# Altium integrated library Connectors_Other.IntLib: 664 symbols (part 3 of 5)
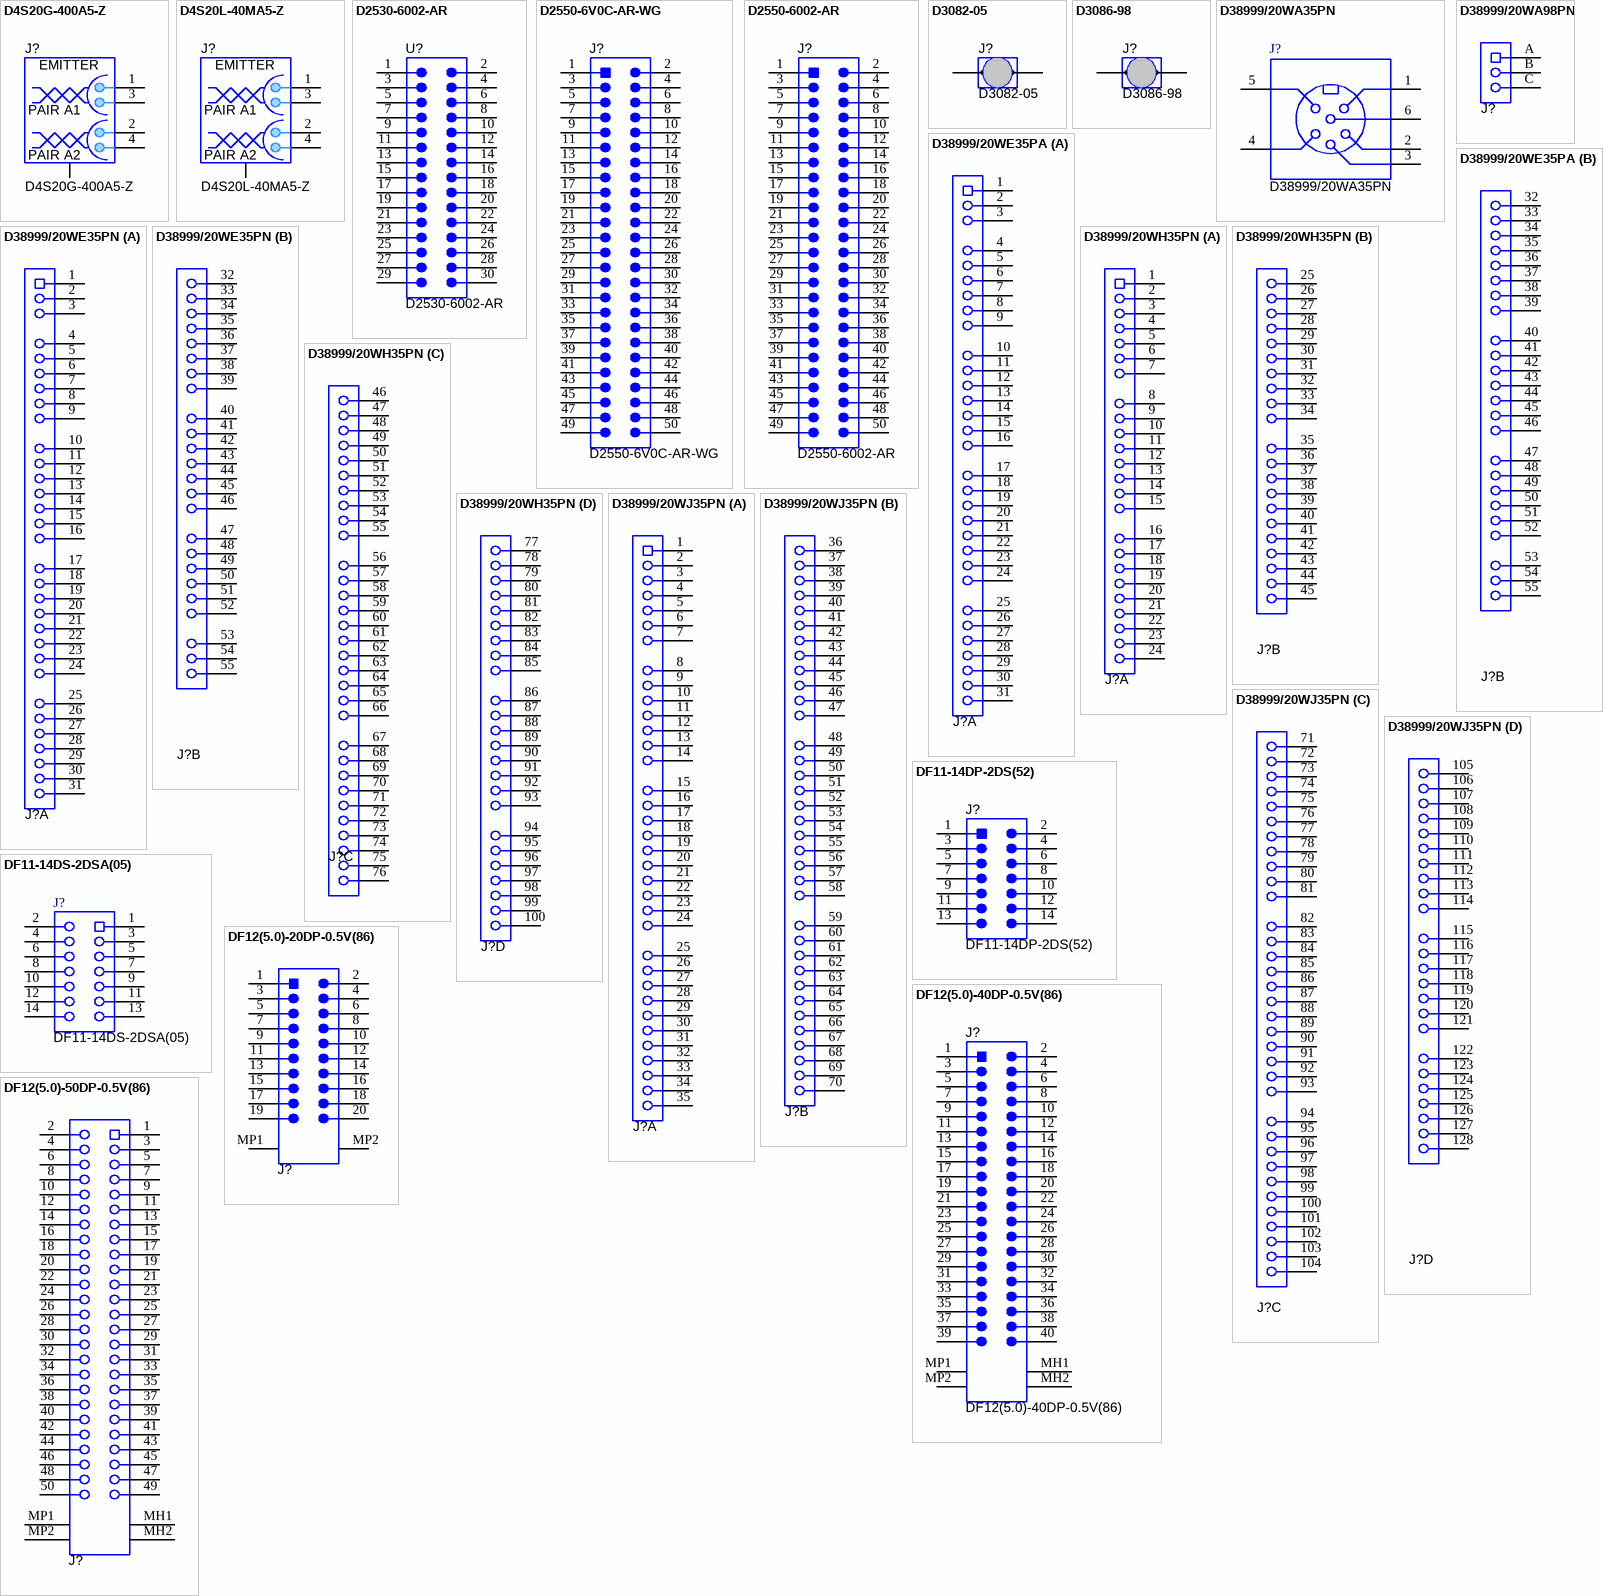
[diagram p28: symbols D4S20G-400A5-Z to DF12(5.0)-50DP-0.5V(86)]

## D3086-98
designator J?
1MM INSULATED SHORTING PLUG, TH; Manufacturer: Harwin; SymbolCreator: a0799628; CompType: Jumper Wire; Pitch_mm: 5.08; Row_Count: 1; ContactFinish: Gold; Green_Lifecycle: Active; Green_REACh: Passed
footprint Harwin_D3086-98
pins: 1, 2

## D38999/20WA35PN
designator J?
Receptacle, A35, 6 Pos, Gold, TH; Manufacturer: Amphenol Aerospace; SymbolCreator: x0208326; CompType: Connector; Gender: Female; Current_A: 5
footprint Amphenol_D38999_20WA35PN
pins: 1, 2, 3  , 4  , 5  , 6  

## D38999/20WA98PN
designator J?  (value not drawn)
Receptacle, A98, 3 Pos, Gold, TH; Manufacturer: Amphenol Aerospace; SymbolCreator: Altium; CompType: Connector; Gender: Female; Current_A: 7.5
footprint Amphenol_D38999_20WA98PN
pins: A, B, C

## D38999/20WE35PA
designator J?  (value not drawn)
Receptacle, E35, 55 Pos, Gold, TH; Manufacturer: Amphenol Aerospace; SymbolCreator: Altium; CompType: Connector; Gender: Female; Current_A: 5; Voltage_V: 550
footprint Amphenol_D38999_20WE35
part A pins: 1, 2, 3, 4, 5, 6, 7, 8, 9, 10, 11, 12, 13, 14, 15, 16, 17, 18, 19, 20, 21, 22, 23, 24, 25, 26, 27, 28, 29, 30, 31
part B pins: 32, 33, 34, 35, 36, 37, 38, 39, 40, 41, 42, 43, 44, 45, 46, 47, 48, 49, 50, 51, 52, 53, 54, 55

## D38999/20WE35PN
designator J?  (value not drawn)
Receptacle, E35, 55 Pos, Gold, TH; Manufacturer: Amphenol Aerospace; SymbolCreator: Altium; CompType: Connector; Gender: Female; Current_A: 5
footprint Amphenol_D38999_20WE35
part A pins: 1, 2, 3, 4, 5, 6, 7, 8, 9, 10, 11, 12, 13, 14, 15, 16, 17, 18, 19, 20, 21, 22, 23, 24, 25, 26, 27, 28, 29, 30, 31
part B pins: 32, 33, 34, 35, 36, 37, 38, 39, 40, 41, 42, 43, 44, 45, 46, 47, 48, 49, 50, 51, 52, 53, 54, 55

## D38999/20WH35PN
designator J?  (value not drawn)
Receptacle, H35, 100 Pos, Gold, TH; Manufacturer: Amphenol Aerospace; SymbolCreator: Altium; CompType: Connector; Gender: Female; Current_A: 5; Voltage_V: 550
footprint Amphenol_D38999_20WH35PN
part A pins: 1, 2, 3, 4, 5, 6, 7, 8, 9, 10, 11, 12, 13, 14, 15, 16, 17, 18, 19, 20, 21, 22, 23, 24
part B pins: 25, 26, 27, 28, 29, 30, 31, 32, 33, 34, 35, 36, 37, 38, 39, 40, 41, 42, 43, 44, 45
part C pins: 46, 47, 48, 49, 50, 51, 52, 53, 54, 55, 56, 57, 58, 59, 60, 61, 62, 63, 64, 65, 66, 67, 68, 69, 70, 71, 72, 73, 74, 75, 76
part D pins: 77, 78, 79, 80, 81, 82, 83, 84, 85, 86, 87, 88, 89, 90, 91, 92, 93, 94, 95, 96, 97, 98, 99, 100

## D38999/20WJ35PN
designator J?  (value not drawn)
Receptacle, J35, 128 Pos, Gold, TH; Manufacturer: Amphenol Aerospace; SymbolCreator: Altium; CompType: Connector; Gender: Female; Current_A: 5; Voltage_V: 550
footprint Amphenol_D38999_20WJ35PN
part A pins: 1, 2, 3, 4, 5, 6, 7, 8, 9, 10, 11, 12, 13, 14, 15, 16, 17, 18, 19, 20, 21, 22, 23, 24, 25, 26, 27, 28, 29, 30, 31, 32, 33, 34, 35
part B pins: 36, 37, 38, 39, 40, 41, 42, 43, 44, 45, 46, 47, 48, 49, 50, 51, 52, 53, 54, 55, 56, 57, 58, 59, 60, 61, 62, 63, 64, 65, 66, 67, 68, 69, 70
part C pins: 71, 72, 73, 74, 75, 76, 77, 78, 79, 80, 81, 82, 83, 84, 85, 86, 87, 88, 89, 90, 91, 92, 93, 94, 95, 96, 97, 98, 99, 100, 101, 102, 103, 104
part D pins: 105, 106, 107, 108, 109, 110, 111, 112, 113, 114, 115, 116, 117, 118, 119, 120, 121, 122, 123, 124, 125, 126, 127, 128

## DF11-14DP-2DS(52)
designator J?
Header (shrouded), 2 mm, 7x2, R/A, TH; Manufacturer: Hirose Electric Co. Ltd.; SymbolCreator: a0412235
footprint Hirose_DF11-14DP-2DS_52
pins: 1, 2, 3, 4, 5, 6, 7, 8, 9, 10, 11, 12, 13, 14

## DF11-14DS-2DSA(05)
designator J?
Receptacle, 2mm, 7x2, Gold, TH; Manufacturer: Hirose Electric Co. Ltd.; SymbolCreator: a0412235; Green_Lifecycle: Not Set; Green_REACh: Incomplete
footprint Hirose_DF11-14DS-2DSA[05]
pins: 1, 2, 3, 4, 5, 6, 7, 8, 9, 10, 11, 12, 13, 14

## DF12(5.0)-20DP-0.5V(86)
designator J?  (value not drawn)
Header(Shrouded), 0.5mm, 10x2, Gold, SMT; Manufacturer: Hirose Electric Co. Ltd.; SymbolCreator: Altium; Pitch_mm: 0.5; Gender: Male; Shrouded: Y; Row_Count: 2; Current_A: 0.3; Voltage_V: 50
footprint Hirose_DF12_5_0-20DP-0_5V
pins: 1, 2, 3, 4, 5, 6, 7, 8, 9, 10, 11, 12, 13, 14, 15, 16, 17, 18, 19, 20, MP1, MP2

## DF12(5.0)-40DP-0.5V(86)
designator J?
Header(shrouded), 0.5mm, 20x2, Gold, SMT; Manufacturer: Hirose Electric Co. Ltd.; SymbolCreator: Altium; Pitch_mm: 0.5; Gender: Male; Shrouded: Y; Row_Count: 2; Current_A: 0.3; Voltage_V: 50
footprint Hirose_DF12_5_0-40DP-0_5V
pins: 1, 2, 3, 4, 5, 6, 7, 8, 9, 10, 11, 12, 13, 14, 15, 16, 17, 18, 19, 20, 21, 22, 23, 24, 25, 26, 27, 28, 29, 30, 31, 32, 33, 34, 35, 36, 37, 38, 39, 40, MH1, MH2, MP1, MP2

## DF12(5.0)-50DP-0.5V(86)
designator J?  (value not drawn)
Receptacle, 0.5mm, 25x2, Gold, SMT; Manufacturer: Hirose Electric Co. Ltd.; SymbolCreator: Altium; Pitch_mm: 0.5; Gender: Female; Row_Count: 2; Current_A: 0.3; Voltage_V: 50; Cert_UL: Y
footprint Hirose_DF12_5_0-50DP-0_5V
footprint Hirose_DF12_5_0-50DP-0_5V_Reverse
pins: 1, 2, 3, 4, 5, 6, 7, 8, 9, 10, 11, 12, 13, 14, 15, 16, 17, 18, 19, 20, 21, 22, 23, 24, 25, 26, 27, 28, 29, 30, 31, 32, 33, 34, 35, 36, 37, 38, 39, 40, 41, 42, 43, 44, 45, 46, 47, 48, 49, 50, MH1, MH2, MP1, MP2

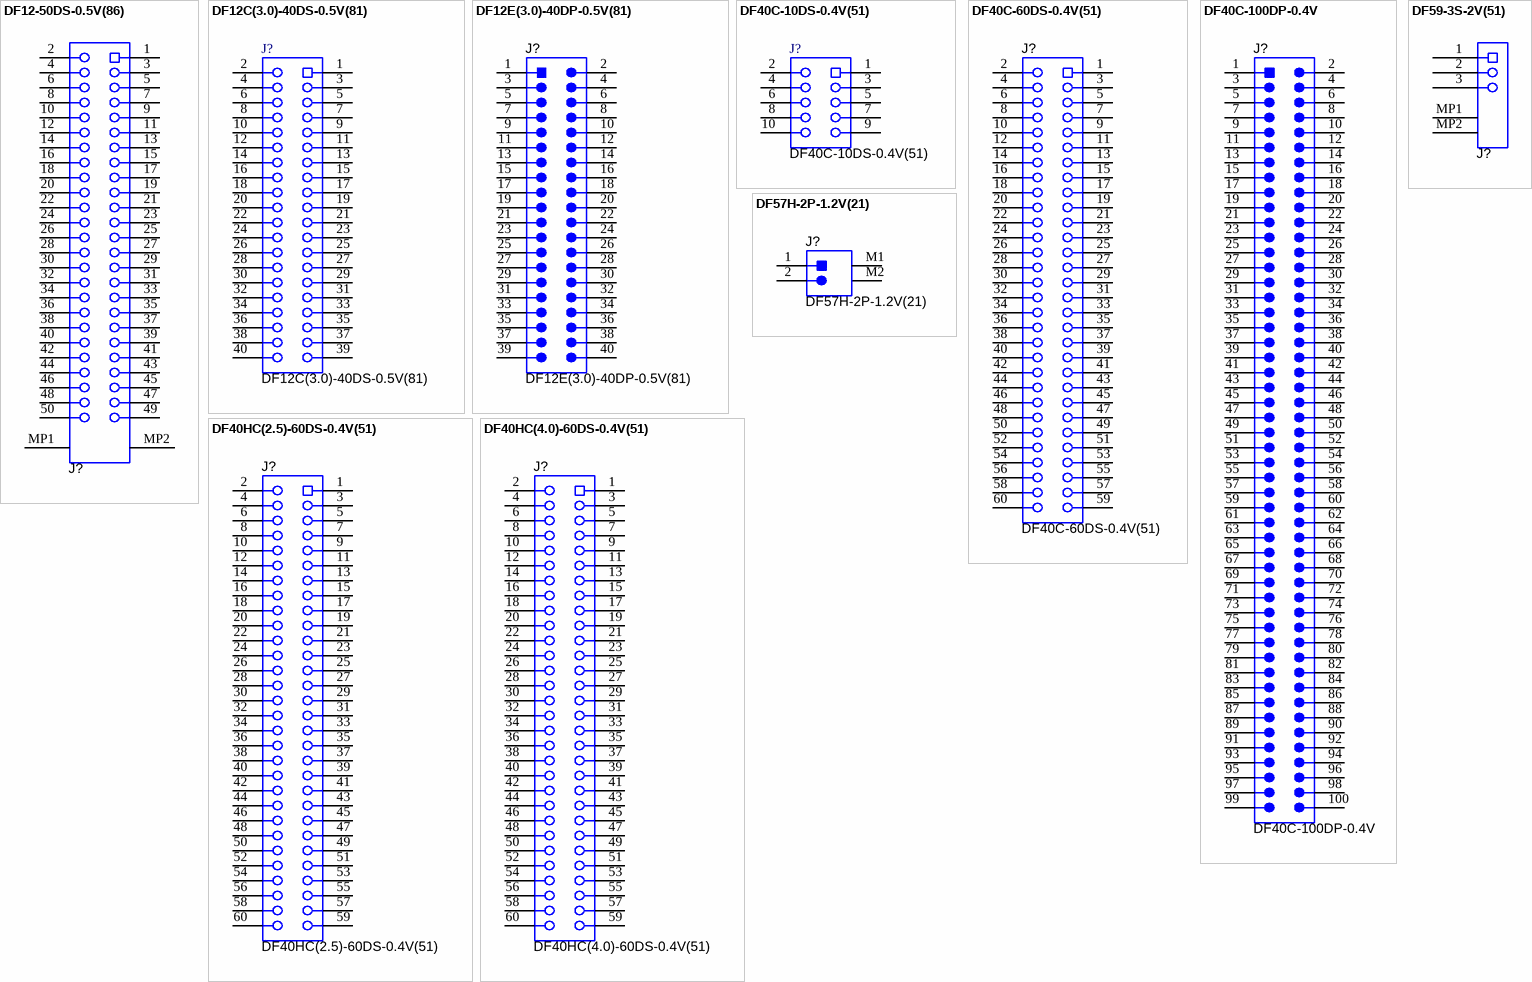
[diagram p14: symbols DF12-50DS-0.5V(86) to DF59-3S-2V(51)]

## DF12-50DS-0.5V(86)
designator J?  (value not drawn)
Receptacle, 0.5mm, 25x2, Gold, SMT; Manufacturer: Hirose Electric Co. Ltd.; SymbolCreator: Altium; Pitch_mm: 0.5; Gender: Female; Row_Count: 2; Current_A: 0.3; Voltage_V: 50; Cert_UL: Y
footprint Hirose_DF12-50DS-0_5V
pins: 1, 2, 3, 4, 5, 6, 7, 8, 9, 10, 11, 12, 13, 14, 15, 16, 17, 18, 19, 20, 21, 22, 23, 24, 25, 26, 27, 28, 29, 30, 31, 32, 33, 34, 35, 36, 37, 38, 39, 40, 41, 42, 43, 44, 45, 46, 47, 48, 49, 50, MP1, MP2

## DF12C(3.0)-40DS-0.5V(81)
designator J?
Receptacle, 0.5mm, 20x2, Gold, SMT; Manufacturer: Hirose Electric Co. Ltd.; SymbolCreator: a0412235; Pitch_mm: 0.5; Gender: Female; Row_Count: 2; Current_A: 0.3; Voltage_V: 50; Cert_UL: Y
footprint Hirose_DF12C_3_0-40DS-0_5V_81
pins: 1, 2, 3, 4, 5, 6, 7, 8, 9, 10, 11, 12, 13, 14, 15, 16, 17, 18, 19, 20, 21, 22, 23, 24, 25, 26, 27, 28, 29, 30, 31, 32, 33, 34, 35, 36, 37, 38, 39, 40

## DF12E(3.0)-40DP-0.5V(81)
designator J?
Header, 0.5mm, 20x2, Gold, SMT; Manufacturer: Hirose Electric Co. Ltd.; SymbolCreator: a0412235; Pitch_mm: 0.5; Gender: Male; Row_Count: 2; Current_A: 0.3; Voltage_V: 50; Cert_UL: Y
footprint Hirose_DF12E_3_0-40DP-0_5V_81
pins: 1, 2, 3, 4, 5, 6, 7, 8, 9, 10, 11, 12, 13, 14, 15, 16, 17, 18, 19, 20, 21, 22, 23, 24, 25, 26, 27, 28, 29, 30, 31, 32, 33, 34, 35, 36, 37, 38, 39, 40

## DF40C-10DS-0.4V(51)
designator J?
Receptacle, FPC, 0.4mm, 5x2, Gold, SMT; Manufacturer: Hirose Electric Co. Ltd.; SymbolCreator: a0412235; CompType: FFC or FPC
footprint Hirose_DF40C-10DS-0.4V
pins: 1, 2, 3, 4, 5, 6, 7, 8, 9, 10

## DF40C-60DS-0.4V(51)
designator J?
Receptacle, 0.4mm, 30x2, Gold, SMT; Manufacturer: Hirose Electric Co. Ltd.; SymbolCreator: Altium; Pitch_mm: 0.4; Gender: Female; Row_Count: 2; Current_A: 0.3; Voltage_V: 30; Cert_UL: Y
footprint Hirose_DF40C-60DS-0_4V
pins: 1, 2, 3, 4, 5, 6, 7, 8, 9, 10, 11, 12, 13, 14, 15, 16, 17, 18, 19, 20, 21, 22, 23, 24, 25, 26, 27, 28, 29, 30, 31, 32, 33, 34, 35, 36, 37, 38, 39, 40, 41, 42, 43, 44, 45, 46, 47, 48, 49, 50, 51, 52, 53, 54, 55, 56, 57, 58, 59, 60
1 alternate drawing of the same symbol

## DF40C-100DP-0.4V
designator J?
Header, 0.4mm, 50x2, Gold, SMT; Manufacturer: Hirose Electric Co. Ltd.; SymbolCreator: a0799628
footprint CONN_DF40C-100DP-0_4V
pins: 1, 2, 3, 4, 5, 6, 7, 8, 9, 10, 11, 12, 13, 14, 15, 16, 17, 18, 19, 20, 21, 22, 23, 24, 25, 26, 27, 28, 29, 30, 31, 32, 33, 34, 35, 36, 37, 38, 39, 40, 41, 42, 43, 44, 45, 46, 47, 48, 49, 50, 51, 52, 53, 54, 55, 56, 57, 58, 59, 60, 61, 62, 63, 64, 65, 66, 67, 68, 69, 70, 71, 72, 73, 74, 75, 76, 77, 78, 79, 80, 81, 82, 83, 84, 85, 86, 87, 88, 89, 90, 91, 92, 93, 94, 95, 96, 97, 98, 99, 100

## DF40HC(2.5)-60DS-0.4V(51)
designator J?
Receptacle, 0.4mm, 30x2, Gold, SMT; Manufacturer: Hirose Electric Co. Ltd.; SymbolCreator: Altium; Pitch_mm: 0.4; Gender: Female; Row_Count: 2; Current_A: 0.3; Voltage_V: 30; Cert_UL: Y
footprint Hirose_DF40HC_2_5-60DS-0_4V
pins: 1, 2, 3, 4, 5, 6, 7, 8, 9, 10, 11, 12, 13, 14, 15, 16, 17, 18, 19, 20, 21, 22, 23, 24, 25, 26, 27, 28, 29, 30, 31, 32, 33, 34, 35, 36, 37, 38, 39, 40, 41, 42, 43, 44, 45, 46, 47, 48, 49, 50, 51, 52, 53, 54, 55, 56, 57, 58, 59, 60
1 alternate drawing of the same symbol

## DF40HC(4.0)-60DS-0.4V(51)
designator J?
Receptacle, 0.4mm, 30x2, Gold, SMT; Manufacturer: Hirose Electric Co. Ltd.; SymbolCreator: Altium; Pitch_mm: 0.4; Gender: Female; Row_Count: 2; Current_A: 0.3; Voltage_V: 30; Cert_UL: Y
footprint Hirose_DF40HC-4_0-60DS-0_4V
footprint Hirose_DF40HC-4_0-60DS-0_4V_Reverse
pins: 1, 2, 3, 4, 5, 6, 7, 8, 9, 10, 11, 12, 13, 14, 15, 16, 17, 18, 19, 20, 21, 22, 23, 24, 25, 26, 27, 28, 29, 30, 31, 32, 33, 34, 35, 36, 37, 38, 39, 40, 41, 42, 43, 44, 45, 46, 47, 48, 49, 50, 51, 52, 53, 54, 55, 56, 57, 58, 59, 60
1 alternate drawing of the same symbol

## DF57H-2P-1.2V(21)
designator J?
Header, 1.2mm, 2x1, Tin, SMT; Manufacturer: Hirose Electric Co. Ltd.; SymbolCreator: x0208326; Pitch_mm: 1.2; Gender: Male; Shrouded: N; Row_Count: 1; Current_A: 2.5; Voltage_V: 50; Cert_CSA: Y
footprint Hirose_DF57H-2P-1_2V_21
pins: 1, 2, M1, M2

## DF59-3S-2V(51)
designator J?  (value not drawn)
Receptacle, 2mm, 3x1, Gold, Natural, SMT; Manufacturer: Hirose Electric Co. Ltd.; SymbolCreator: Altium; Pitch_mm: 2; Gender: Female; Row_Count: 1; Current_A: 3; Voltage_V: 230; Cert_UL: Y
footprint Hirose_DF59-3S-2V_51
pins: 1, 2, 3, MP1, MP2

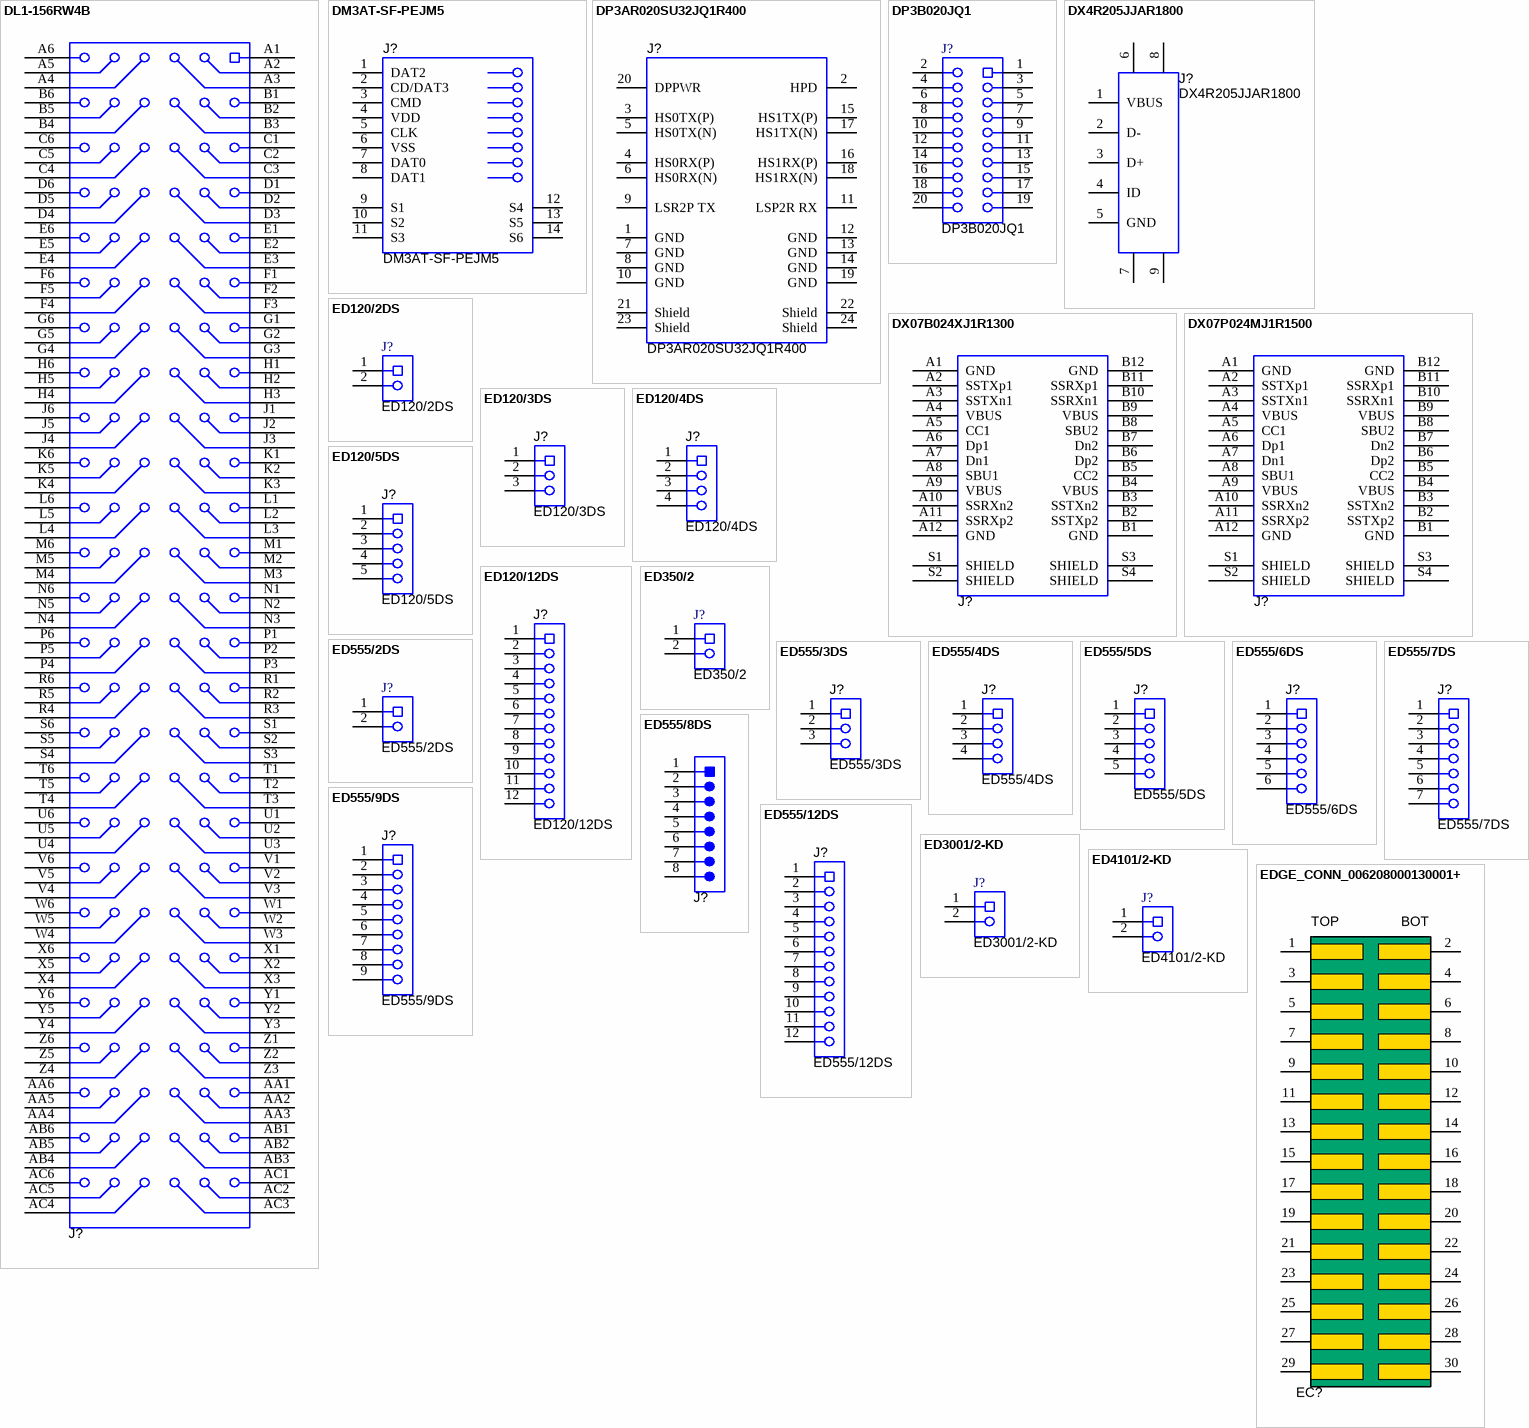
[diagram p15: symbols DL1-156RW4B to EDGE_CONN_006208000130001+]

## DL1-156RW4B
designator J?  (value not drawn)
Receptacle, 2.54mm, 26x6, Gold, TH; Manufacturer: ITT Cannon; SymbolCreator: Altium; Pitch_mm: 2.54; Gender: Female; Row_Count: 6; Current_A: 5; Cert_UL: Y
footprint Cannon_DL1-156RW4
pins: A1, A2, A3, A4, A5, A6, AA1, AA2, AA3, AA4, AA5, AA6, AB1, AB2, AB3, AB4, AB5, AB6, AC1, AC2, AC3, AC4, AC5, AC6, B1, B2, B3, B4, B5, B6, C1, C2, C3, C4, C5, C6, D1, D2, D3, D4, D5, D6, E1, E2, E3, E4, E5, E6, F1, F2, F3, F4, F5, F6, G1, G2, G3, G4, G5, G6, H1, H2, H3, H4, H5, H6, J1, J2, J3, J4, J5, J6, K1, K2, K3, K4, K5, K6, L1, L2, L3, L4, L5, L6, M1, M2, M3, M4, M5, M6, N1, N2, N3, N4, N5, N6, P1, P2, P3, P4, P5, P6, R1, R2, R3, R4, R5, R6, S1, S2, S3, S4, S5, S6, T1, T2, T3, T4, T5, T6, U1, U2, U3, U4, U5, U6, V1, V2, V3, V4, V5, V6, W1, W2, W3, W4, W5, W6, X1, X2, X3, X4, X5, X6, Y1, Y2, Y3, Y4, Y5, Y6, Z1, Z2, Z3, Z4, Z5, Z6

## DM3AT-SF-PEJM5
designator J?
Connector, Micro SD, Top, SMD; Manufacturer: Hirose Electric Co. Ltd.; SymbolCreator: a0412235; Green_Lifecycle: Active; Green_REACh: Passed
footprint Hirose_DM3AT-SF-PEJM5
pins: 1 DAT2, 2 CD/DAT3, 3 CMD, 4 VDD, 5 CLK, 6 VSS, 7 DAT0, 8 DAT1, 9 S1, 10 S2, 11 S3, 12 S4, 13 S5, 14 S6

## DP3AR020SU32JQ1R400
designator J?
Receptacle, 20 Pins, R/A, TH; Manufacturer: JAE Electronics; SymbolCreator: Altium; Gender: Female
footprint JAE_DP3AR020SU32JQ1
pins: 1 GND, 2 HPD, 3 HS0TX(P), 4 HS0RX(P), 5 HS0TX(N), 6 HS0RX(N), 7 GND, 8 GND, 9 LSR2P TX, 10 GND, 11 LSP2R RX, 12 GND, 13 GND, 14 GND, 15 HS1TX(P), 16 HS1RX(P), 17 HS1TX(N), 18 HS1RX(N), 19 GND, 20 DPPWR, 21 Shield, 22 Shield, 23 Shield, 24 Shield

## DP3B020JQ1
designator J?
Edge Connector, 20pos; Manufacturer: JAE Electronics; SymbolCreator: a0412235; CompType: Receptacle
footprint CONN_EDGE_DP3B020JQ1
pins: 1, 2, 3, 4, 5, 6, 7, 8, 9, 10, 11, 12, 13, 14, 15, 16, 17, 18, 19, 20

## DX4R205JJAR1800
designator J?
Connector, Receptacle, Micro-USB Type AB, R/A, Bottom Mount SMT; Manufacturer: JAE Electronics; SymbolCreator: a0799628; CompType: USB; Gender: Female; Green_Lifecycle: Not Set; Green_REACh: Incomplete
footprint CONN_USB_DX4R205JJA
pins: 1 VBUS, 2 D-, 3 D+, 4 ID, 5 GND, 6, 7, 8, 9
1 alternate drawing of the same symbol

## DX07B024XJ1R1300
designator J?  (value not drawn)
Connector, USB 3.1 Type C, R/A, SMT; Manufacturer: JAE Electronics; SymbolCreator: Altium; Pitch_mm: 0.5; Gender: Female; Current_A: 5; Voltage_V: 20
footprint JAE_DX07B024XJ1R1300
pins: A1 GND, A2 SSTXp1, A3 SSTXn1, A4 VBUS, A5 CC1, A6 Dp1, A7 Dn1, A8 SBU1, A9 VBUS, A10 SSRXn2, A11 SSRXp2, A12 GND, B1 GND, B2 SSTXp2, B3 SSTXn2, B4 VBUS, B5 CC2, B6 Dp2, B7 Dn2, B8 SBU2, B9 VBUS, B10 SSRXn1, B11 SSRXp1, B12 GND, S1 SHIELD, S2 SHIELD, S3 SHIELD, S4 SHIELD

## DX07P024MJ1R1500
designator J?  (value not drawn)
Plug, USB3.1, TYPE-C, R/A, SMT; Manufacturer: JAE Electronics; SymbolCreator: Altium; CompType: USB; Pitch_mm: 0.5; Gender: Male; Shrouded: Y; Row_Count: 2; ContactFinish: Gold; Current_A: 5; Voltage_V: 20; Green_Lifecycle: Not Set; Green_REACh: Incomplete
footprint JAE_DX07P024MJ1
pins: A1 GND, A2 SSTXp1, A3 SSTXn1, A4 VBUS, A5 CC1, A6 Dp1, A7 Dn1, A8 SBU1, A9 VBUS, A10 SSRXn2, A11 SSRXp2, A12 GND, B1 GND, B2 SSTXp2, B3 SSTXn2, B4 VBUS, B5 CC2, B6 Dp2, B7 Dn2, B8 SBU2, B9 VBUS, B10 SSRXn1, B11 SSRXp1, B12 GND, S1 SHIELD, S2 SHIELD, S3 SHIELD, S4 SHIELD

## ED120/2DS
designator J?
Terminal Block, 5.08 mm, 2x1, Brass, TH; Manufacturer: On-Shore Technology; SymbolCreator: a0412235; Pitch_mm: 5.08; Gender: Female; Shrouded: N; Row_Count: 1; Current_A: 15; Voltage_V: 300; Cert_CULUS: Y; Green_Lifecycle: Not Set; Green_REACh: Incomplete
footprint On-Shore_ED120_2DS
pins: 1, 2

## ED120/3DS
designator J?
Terminal Block, 5.08 mm, 3x1, Brass, TH; Manufacturer: On-Shore Technology; SymbolCreator: a0412235; Pitch_mm: 5.08; Gender: Female; Shrouded: N; Row_Count: 1; Current_A: 15; Voltage_V: 300; Cert_CULUS: Y; Green_Lifecycle: Not Set; Green_REACh: Incomplete
footprint On-Shore_ED120_3DS
pins: 1, 2, 3

## ED120/4DS
designator J?
Terminal Block, 5.08 mm, 4x1, Brass, TH; Manufacturer: On-Shore Technology; SymbolCreator: a0411947; Pitch_mm: 5.08; Gender: Female; Shrouded: N; Row_Count: 1; Current_A: 15; Voltage_V: 300; Cert_CULUS: Y; Green_Lifecycle: Not Set; Green_REACh: Incomplete
footprint On-Shore_ED120_4DS
pins: 1, 2, 3, 4

## ED120/5DS
designator J?
Terminal Block, 5.08 mm, 5x1, Brass, TH; Manufacturer: On-Shore Technology; SymbolCreator: a0412235; Pitch_mm: 5.08; Gender: Female; Shrouded: N; Row_Count: 1; Current_A: 15; Voltage_V: 300; Cert_CULUS: Y
footprint On-Shore_ED120_5DS
pins: 1, 2, 3, 4, 5

## ED120/12DS
designator J?
Terminal Block, 5.08 mm, 12x1, Brass, TH; Manufacturer: On-Shore Technology; SymbolCreator: a0412235; Pitch_mm: 5.08; Gender: Female; Shrouded: N; Row_Count: 1; Current_A: 15; Voltage_V: 300; Cert_CULUS: Y
footprint On-Shore_ED120_12DS
pins: 1, 2, 3, 4, 5, 6, 7, 8, 9, 10, 11, 12

## ED350/2
designator J?
Terminal Block, 5mm, 2-pole, TH; Manufacturer: On-Shore Technology; SymbolCreator: a0412235; Green_Lifecycle: Not Set; Green_REACh: Incomplete
footprint On-Shore_ED350_2
pins: 1, 2

## ED555/2DS
designator J?
Terminal Block, 3.5mm Pitch, 2x1, TH; Manufacturer: On-Shore Technology; SymbolCreator: a0412235; Pitch_mm: 3.5; Gender: Female; Shrouded: N; Row_Count: 1; ContactFinish: Brass; Current_A: 6; Voltage_V: 150; Cert_CULUS: Y; Green_Lifecycle: Active; Green_REACh: Passed
footprint TERM_BLK_ED555-2DS
pins: 1, 2

## ED555/3DS
designator J?
Terminal Block, 3.5mm Pitch, 3x1, TH; Manufacturer: On-Shore Technology; SymbolCreator: a0412235; Pitch_mm: 3.5; Gender: Female; Shrouded: N; Row_Count: 1; ContactFinish: Brass; Current_A: 6; Voltage_V: 150; Cert_CULUS: Y; Green_Lifecycle: Active; Green_REACh: Passed
footprint TERM_BLK_ED555-3DS
pins: 1, 2, 3

## ED555/4DS
designator J?
Terminal Block, 3.5mm Pitch, 4x1, TH; Manufacturer: On-Shore Technology; SymbolCreator: a0411947; Pitch_mm: 3.5; Gender: Female; Shrouded: N; Row_Count: 1; ContactFinish: Brass; Current_A: 6; Voltage_V: 150; Cert_CULUS: Y; Green_Lifecycle: Not Set; Green_REACh: Incomplete
footprint TERM_BLK_ED555-4DS
pins: 1, 2, 3, 4

## ED555/5DS
designator J?
Terminal Block, 3.5mm Pitch, 5x1, TH; Manufacturer: On-Shore Technology; SymbolCreator: a0412235; Pitch_mm: 3.5; Gender: Female; Shrouded: N; Row_Count: 1; ContactFinish: Brass; Current_A: 6; Voltage_V: 150; Cert_CULUS: Y; Green_Lifecycle: Not Set; Green_REACh: Incomplete
footprint TERM_BLK_ED555-5DS
pins: 1, 2, 3, 4, 5

## ED555/6DS
designator J?
Terminal Block, 3.5mm Pitch, 6x1, TH; Manufacturer: On-Shore Technology; SymbolCreator: a0411947; Pitch_mm: 3.5; Gender: Female; Shrouded: N; Row_Count: 1; ContactFinish: Brass; Current_A: 6; Voltage_V: 150; Cert_CULUS: Y; Green_Lifecycle: Not Set; Green_REACh: Incomplete
footprint TERM_BLK_ED555-6DS
pins: 1, 2, 3, 4, 5, 6

## ED555/7DS
designator J?
Terminal Block, 3.5mm Pitch, 7x1, TH; Manufacturer: On-Shore Technology; SymbolCreator: Altium; Pitch_mm: 3.5; Gender: Female; Shrouded: N; Row_Count: 1; ContactFinish: Brass; Current_A: 6; Voltage_V: 150; Cert_CULUS: Y; Green_Lifecycle: Not Set; Green_REACh: Incomplete
footprint On-Shore_ED555-7DS
pins: 1, 2, 3, 4, 5, 6, 7

## ED555/8DS
designator J?  (value not drawn)
Terminal Block, 3.5mm, 8-Pos, TH; Manufacturer: On-Shore Technology; SymbolCreator: a0411947; Pitch_mm: 3.5; Gender: Male; Shrouded: Y; Row_Count: 1; ContactFinish: Brass; Green_Lifecycle: Not Set; Green_REACh: Incomplete
footprint On-Shore_ED555_8DS
pins: 1, 2, 3, 4, 5, 6, 7, 8

## ED555/9DS
designator J?
Terminal Block, 3.5mm, 9x1, R/A, TH; Manufacturer: On-Shore Technology; SymbolCreator: x0208325; Pitch_mm: 3.5; Gender: Female; Row_Count: 1; Current_A: 6; Voltage_V: 150; Cert_UL: Y; Green_Lifecycle: Not Set; Green_REACh: Incomplete
footprint On-Shore_ED555_9DS
pins: 1, 2, 3, 4, 5, 6, 7, 8, 9

## ED555/12DS
designator J?
Terminal Block, 3.5mm, 12-Pos, TH; Manufacturer: On-Shore Technology; SymbolCreator: a0412235; Pitch_mm: 3.5; Gender: Female; Row_Count: 1; Current_A: 6; Voltage_V: 150; Cert_UL: Y
footprint On-Shore_ED555_12DS
pins: 1, 2, 3, 4, 5, 6, 7, 8, 9, 10, 11, 12

## ED3001/2-KD
designator J?
Terminal Block, 5mm, 2x1, Cu, 45 degree, TH; Manufacturer: On-Shore Technology; SymbolCreator: a0412235; Pitch_mm: 5; Gender: Female; Row_Count: 1; Current_A: 16; Voltage_V: 300; Cert_UL: Y
footprint On-Shore_ED3001_2-KD
pins: 1, 2

## ED4101/2-KD
designator J?
Terminal Block, 5mm, 2x1, Cu, R/A, TH; Manufacturer: On-Shore Technology; SymbolCreator: a0412235; Pitch_mm: 5; Gender: Female; Row_Count: 1; Current_A: 10; Voltage_V: 300; Cert_UL: Y
footprint On-Shore_ED4101_2-KD
pins: 1, 2

## EDGE_CONN_006208000130001+
designator EC?  (value not drawn)  (no BOM)
Edge Card Connector, 1mm, 15x2; Manufacturer: AVX; SymbolCreator: a0411947; CompType: Card Edge Footprint
footprint Kyocera_Edge_6208_30
pins: 1, 2, 3, 4, 5, 6, 7, 8, 9, 10, 11, 12, 13, 14, 15, 16, 17, 18, 19, 20, 21, 22, 23, 24, 25, 26, 27, 28, 29, 30

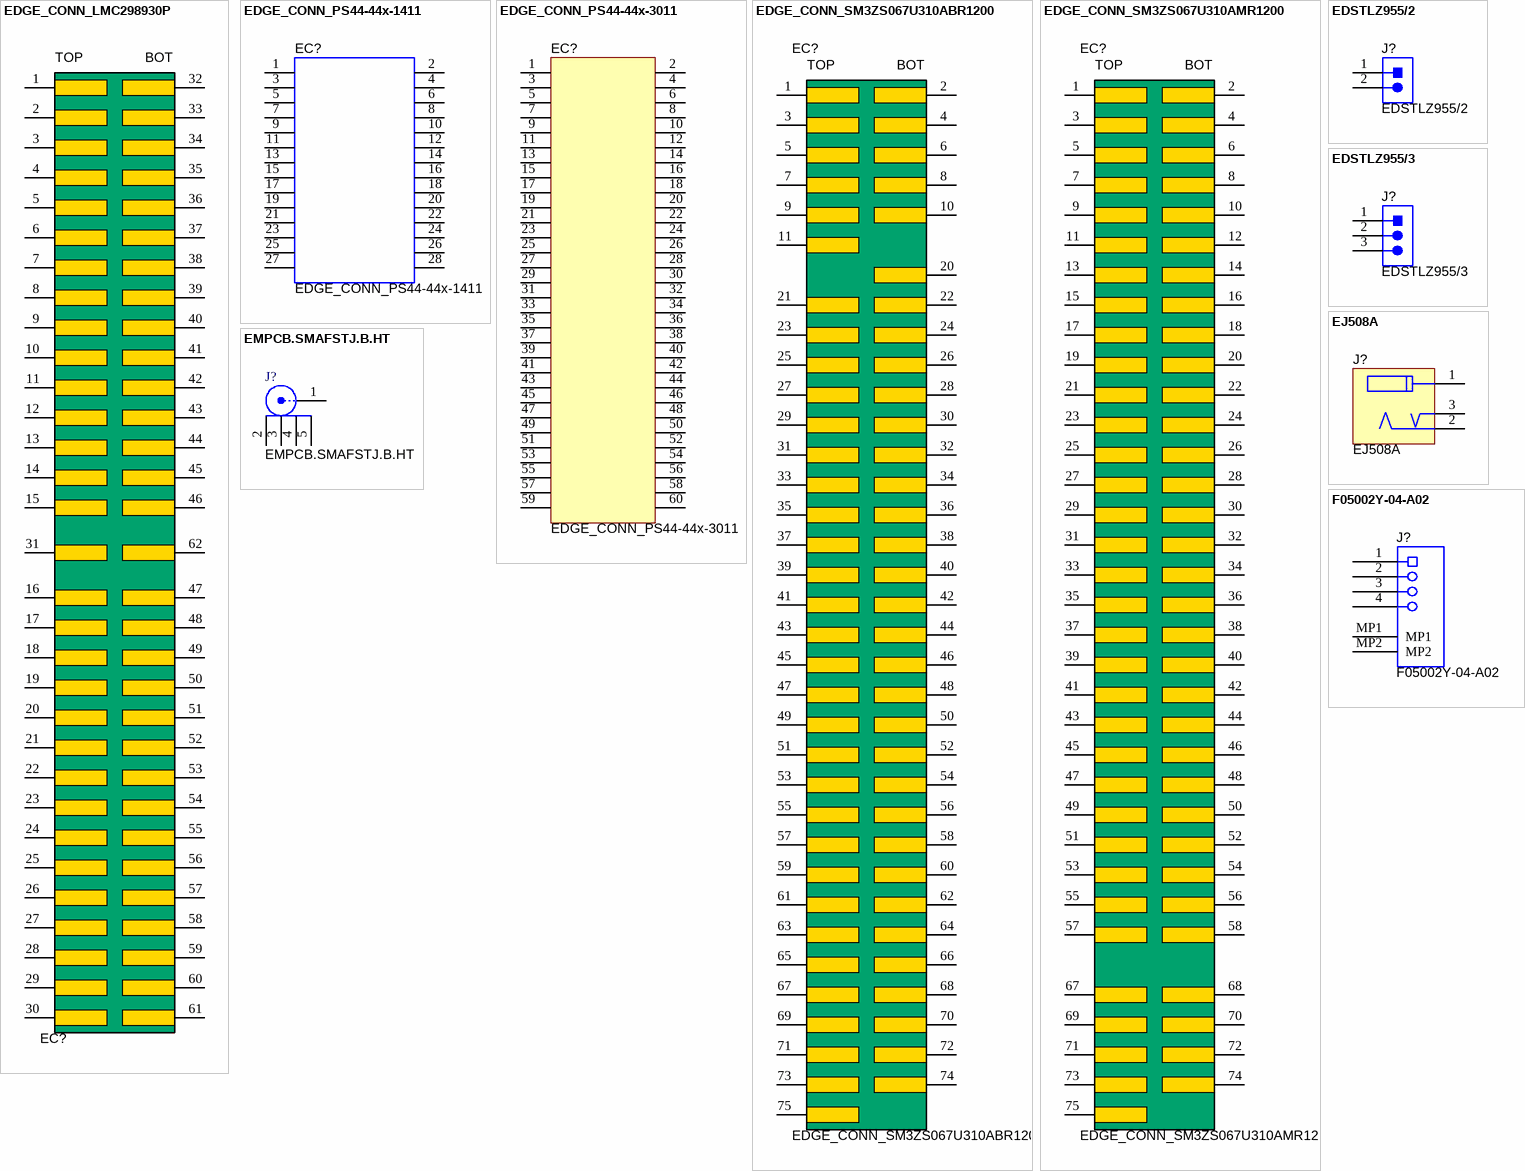
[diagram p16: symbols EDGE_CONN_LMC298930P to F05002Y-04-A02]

## EDGE_CONN_LMC298930P
designator EC?  (value not drawn)  (no BOM)
Edge Connector, 196mil, 62 Pos; Manufacturer: Texas Instruments; SymbolCreator: Altium; CompType: Card Edge Footprint; Pitch_mm: 3.96
footprint TI_EDGE_CONN_LMC298930P
pins: 1, 2, 3, 4, 5, 6, 7, 8, 9, 10, 11, 12, 13, 14, 15, 16, 17, 18, 19, 20, 21, 22, 23, 24, 25, 26, 27, 28, 29, 30, 31, 32, 33, 34, 35, 36, 37, 38, 39, 40, 41, 42, 43, 44, 45, 46, 47, 48, 49, 50, 51, 52, 53, 54, 55, 56, 57, 58, 59, 60, 61, 62

## EDGE_CONN_PS44-44x-1411
designator EC?  (no BOM)
Connector, Card Edge 28-Pos (14x2), 100-mil Pitch; Manufacturer: Yamaichi Electronics; SymbolCreator: a0799721; CompType: Card Edge Footprint; Note: PartNumber and Manufacturer are for matching connector
footprint EDGE_CONN_PS44-44x-1411
pins: 1, 2, 3, 4, 5, 6, 7, 8, 9, 10, 11, 12, 13, 14, 15, 16, 17, 18, 19, 20, 21, 22, 23, 24, 25, 26, 27, 28

## EDGE_CONN_PS44-44x-3011
designator EC?  (no BOM)
Connector, Card Edge 60-Pos (30x2), 100-mil Pitch; Manufacturer: Yamaichi Electronics; SymbolCreator: a0799628/a0412235; CompType: Card Edge Footprint; Note: PartNumber and Manufacturer are for matching connector
footprint EDGE_CONN_PS44-44x-3011
pins: 1, 2, 3, 4, 5, 6, 7, 8, 9, 10, 11, 12, 13, 14, 15, 16, 17, 18, 19, 20, 21, 22, 23, 24, 25, 26, 27, 28, 29, 30, 31, 32, 33, 34, 35, 36, 37, 38, 39, 40, 41, 42, 43, 44, 45, 46, 47, 48, 49, 50, 51, 52, 53, 54, 55, 56, 57, 58, 59, 60

## EDGE_CONN_SM3ZS067U310ABR1200
designator EC?  (no BOM)
Connector, Card Edge 67-Pos, 0.5-mm Pitch, B Key; Manufacturer: JAE Electronics; SymbolCreator: Altium; CompType: Card Edge Footprint
footprint JAE_EDGE_CONN_SM3ZS067U310ABR1200
pins: 1, 2, 3, 4, 5, 6, 7, 8, 9, 10, 11, 20, 21, 22, 23, 24, 25, 26, 27, 28, 29, 30, 31, 32, 33, 34, 35, 36, 37, 38, 39, 40, 41, 42, 43, 44, 45, 46, 47, 48, 49, 50, 51, 52, 53, 54, 55, 56, 57, 58, 59, 60, 61, 62, 63, 64, 65, 66, 67, 68, 69, 70, 71, 72, 73, 74, 75

## EDGE_CONN_SM3ZS067U310AMR1200
designator EC?  (no BOM)
Connector, Card Edge 67-Pos, 0.5-mm Pitch, M Key; Manufacturer: JAE Electronics; SymbolCreator: Altium; CompType: Card Edge Footprint
footprint JAE_EDGE_CONN_SM3ZS067U310AMR1200
pins: 1, 2, 3, 4, 5, 6, 7, 8, 9, 10, 11, 12, 13, 14, 15, 16, 17, 18, 19, 20, 21, 22, 23, 24, 25, 26, 27, 28, 29, 30, 31, 32, 33, 34, 35, 36, 37, 38, 39, 40, 41, 42, 43, 44, 45, 46, 47, 48, 49, 50, 51, 52, 53, 54, 55, 56, 57, 58, 67, 68, 69, 70, 71, 72, 73, 74, 75

## EDSTLZ955/2
designator J?
Header(shrouded), 5.08mm, 2x1, TH; Manufacturer: On-Shore Technology; SymbolCreator: a0412235; Pitch_mm: 5.08; Gender: Male; Shrouded: Y; Row_Count: 1; Current_A: 15; Voltage_V: 300
footprint On-Shore_EDSTLZ955_2
pins: 1, 2
1 alternate drawing of the same symbol

## EDSTLZ955/3
designator J?
Header(shrouded), 5.08mm, 3x1, TH; Manufacturer: On-Shore Technology; SymbolCreator: a0799628; Pitch_mm: 5.08; Gender: Male; Shrouded: Y; Row_Count: 1; Current_A: 15; Voltage_V: 300
footprint On-Shore_EDSTLZ955_3
pins: 1, 2, 3
3 alternate drawings of the same symbol

## EJ508A
designator J?
Power Jack, 2.1x5.5mm, R/A, TH; Manufacturer: Memory Protection Devices; SymbolCreator: a0799628; Gender: Male; Current_A: 5; Voltage_V: 12
footprint Memory_EJ508A
pins: 1, 2, 3

## EMPCB.SMAFSTJ.B.HT
designator J?
SMA(F) Jack, 50 Ohm, SMT; Manufacturer: Taoglas Antenna Solutions; SymbolCreator: X0208326; Gender: Male; ContactFinish: Gold
footprint Taoglas_EMPCB_SMAFSTJ_B_HT
pins: 1, 2, 3, 4, 5

## F05002Y-04-A02
designator J?
Receptacle, 0.5mm, 4x1, R/A, SMT; Manufacturer: Suzhou Jingshi Electronic Technology Co.; SymbolCreator: Altium; Pitch_mm: 0.5; Gender: Female; Row_Count: 1; ContactFinish: SN; Cert_UL: Y
footprint CNJS_F05002Y-04-A
pins: 1, 2, 3, 4, MP1, MP2

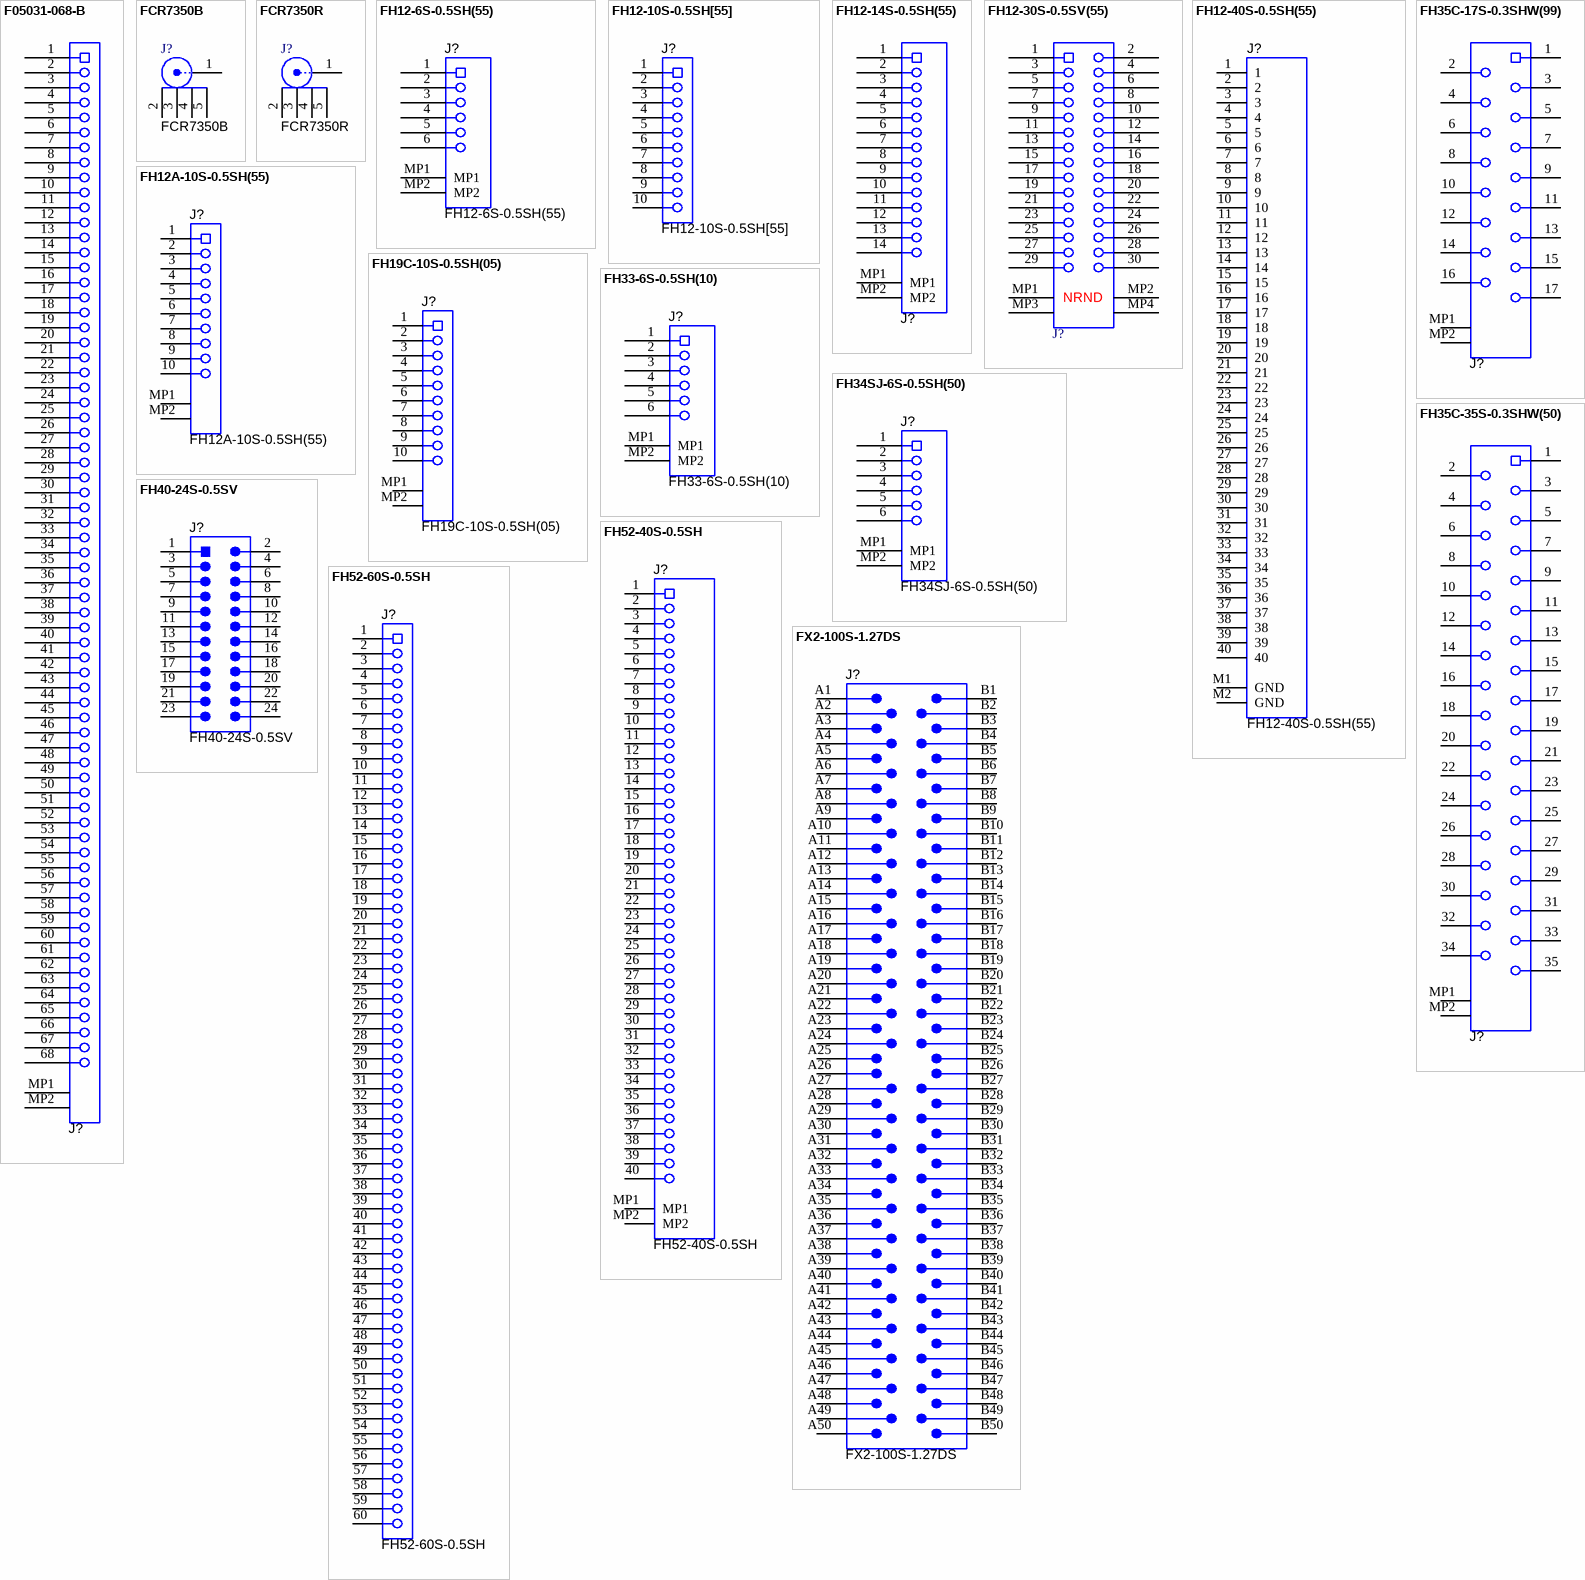
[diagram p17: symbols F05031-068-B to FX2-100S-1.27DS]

## F05031-068-B
designator J?  (value not drawn)
FPC Connector, 0.5mm, 68 Pos, Gold, R/A, SMT; Manufacturer: Skyworth; SymbolCreator: Altium; CompType: FFC or FPC; Pitch_mm: 0.5; Gender: Female; Row_Count: 1; Voltage_V: 50; Cert_UL: Y
footprint DCCT_F05031-068
pins: 1, 2, 3, 4, 5, 6, 7, 8, 9, 10, 11, 12, 13, 14, 15, 16, 17, 18, 19, 20, 21, 22, 23, 24, 25, 26, 27, 28, 29, 30, 31, 32, 33, 34, 35, 36, 37, 38, 39, 40, 41, 42, 43, 44, 45, 46, 47, 48, 49, 50, 51, 52, 53, 54, 55, 56, 57, 58, 59, 60, 61, 62, 63, 64, 65, 66, 67, 68, MP1, MP2

## FCR7350B
designator J?
Panel Socket, 24A, R/A, Gold, TH; Manufacturer: Cliff Electronic Components; SymbolCreator: X0208326; Gender: Female; Current_A: 24; Voltage_V: 1000
footprint Cliff_FCR7350B
pins: 1, 2, 3, 4, 5

## FCR7350R
designator J?
Panel Socket, 24A, R/A, Gold, TH; Manufacturer: Cliff Electronic Components; SymbolCreator: X0208326; Gender: Female; Current_A: 24; Voltage_V: 1000
footprint Cliff_FCR7350R
pins: 1, 2, 3, 4, 5

## FH12-6S-0.5SH(55)
designator J?
Receptacle, 0.5mm, 6x1, Gold, R/A, SMT; Manufacturer: Hirose Electric Co. Ltd.; SymbolCreator: Altium; Pitch_mm: 0.5; Gender: Female; Row_Count: 1; Voltage_V: 50; Cert_UL: Y
footprint Hirose_FH12-6S-0_5SH
pins: 1, 2, 3, 4, 5, 6, MP1, MP2

## FH12-10S-0.5SH[55]
designator J?
Connector, FPC 10 Pos. 9.1x2.0x5.6 mm; Manufacturer: Hirose Electric Co. Ltd.; SymbolCreator: a0411947; CompType: FFC or FPC
footprint Hirose_FH12-10S-0_5SH[55]
pins: 1, 2, 3, 4, 5, 6, 7, 8, 9, 10

## FH12-14S-0.5SH(55)
designator J?  (value not drawn)
Receptacle, 0.5mm, 14x1, Gold, R/A, SMT; Manufacturer: Hirose Electric Co. Ltd.; SymbolCreator: Altium; Pitch_mm: 0.5; Gender: Female; Row_Count: 1; Voltage_V: 50; Cert_UL: Y
footprint Hirose_FH12-14S-0_5SH
pins: 1, 2, 3, 4, 5, 6, 7, 8, 9, 10, 11, 12, 13, 14, MP1, MP2

## FH12-30S-0.5SV(55)
designator J?  (value not drawn)
FFC Connector, 30 POS, 0.5mm, SMT; Manufacturer: Hirose Electric Co. Ltd.; SymbolCreator: Altium; CompType: FFC or FPC; Pitch_mm: 0.5; Gender: Female; Row_Count: 2; ContactFinish: Gold; Voltage_V: 50; Cert_UL: Y
footprint Hirose_FH12-30S-0_5SV_55
pins: 1, 2, 3, 4, 5, 6, 7, 8, 9, 10, 11, 12, 13, 14, 15, 16, 17, 18, 19, 20, 21, 22, 23, 24, 25, 26, 27, 28, 29, 30, MP1, MP2, MP3, MP4

## FH12-40S-0.5SH(55)
designator J?
Connector, FFC/FFP Receptacle, 40-Pos, 1 Row, 0.5mm Pitch, SMT; Manufacturer: Hirose Electric Co. Ltd.; SymbolCreator: a0799721; CompType: FFC or FPC
footprint CONN_FH12-40S-0.5SH(55)
pins: 1, 2, 3, 4, 5, 6, 7, 8, 9, 10, 11, 12, 13, 14, 15, 16, 17, 18, 19, 20, 21, 22, 23, 24, 25, 26, 27, 28, 29, 30, 31, 32, 33, 34, 35, 36, 37, 38, 39, 40, M1 GND, M2 GND

## FH12A-10S-0.5SH(55)
designator J?
FFC Connector , Top, 0.5mm, 10x1, R/A, SMT; Manufacturer: Hirose Electric Co. Ltd.; SymbolCreator: Altium; CompType: FFC or FPC; Pitch_mm: 0.5; Gender: Female; Row_Count: 1; ContactFinish: Gold; Voltage_V: 50
footprint Hirose_FH12A-10S-0_5SH[55]
pins: 1, 2, 3, 4, 5, 6, 7, 8, 9, 10, MP1, MP2

## FH19C-10S-0.5SH(05)
designator J?
Receptacle, 0.5mm, 10x1, Gold, R/A, SMT; Manufacturer: Hirose Electric Co. Ltd.; SymbolCreator: Altium; Pitch_mm: 0.5; Gender: Female; Row_Count: 1
footprint Hirose_FH19C-10S-0_5SH_05
pins: 1, 2, 3, 4, 5, 6, 7, 8, 9, 10, MP1, MP2

## FH33-6S-0.5SH(10)
designator J?
Receptacle, 0.5mm, 6x1, Gold, R/A, SMT; Manufacturer: Hirose Electric Co. Ltd.; SymbolCreator: Altium; Pitch_mm: 0.5; Gender: Female; Row_Count: 1; Voltage_V: 50; Cert_UL: Y
footprint Hirose_FH33-6S-0_5SH
pins: 1, 2, 3, 4, 5, 6, MP1, MP2

## FH34SJ-6S-0.5SH(50)
designator J?
Receptacle, 0.5mm, 6x1, Gold, R/A, SMT; Manufacturer: Hirose Electric Co. Ltd.; SymbolCreator: Altium; Pitch_mm: 0.5; Gender: Female; Row_Count: 1; Voltage_V: 50; Cert_UL: Y
footprint Hirose_FH34SJ-6S-0_5SH
pins: 1, 2, 3, 4, 5, 6, MP1, MP2

## FH35C-17S-0.3SHW(99)
designator J?  (value not drawn)
FPC Connector, 0.30mm, 17 Pos, R/A, SMT; Manufacturer: Hirose Electric Co. Ltd.; SymbolCreator: Altium; CompType: FFC or FPC; Pitch_mm: 0.3; Gender: Female; Row_Count: 2; ContactFinish: Gold; Current_A: 0.2; Voltage_V: 30; Cert_UL: Y
footprint Hirose_FH35C-17S-0_3SHW
pins: 1, 2, 3, 4, 5, 6, 7, 8, 9, 10, 11, 12, 13, 14, 15, 16, 17, MP1, MP2

## FH35C-35S-0.3SHW(50)
designator J?  (value not drawn)
FPC Connector, 0.30mm, 35 Pos, R/A, SMT; Manufacturer: Hirose Electric Co. Ltd.; SymbolCreator: Altium; CompType: FFC or FPC; Pitch_mm: 0.3; Gender: Female; Row_Count: 2; ContactFinish: Gold; Current_A: 0.2; Voltage_V: 30; Cert_UL: Y
footprint Hirose_FH35C-35S-0_3SHW
pins: 1, 2, 3, 4, 5, 6, 7, 8, 9, 10, 11, 12, 13, 14, 15, 16, 17, 18, 19, 20, 21, 22, 23, 24, 25, 26, 27, 28, 29, 30, 31, 32, 33, 34, 35, MP1, MP2

## FH40-24S-0.5SV
designator J?
CONN FPC/FFC 24POS .5MM VERT SMD; Manufacturer: Hirose Electric Co. Ltd.; SymbolCreator: a0412235; CompType: FFC or FPC
footprint Hirose_FH40-24S-0-5SV
pins: 1, 2, 3, 4, 5, 6, 7, 8, 9, 10, 11, 12, 13, 14, 15, 16, 17, 18, 19, 20, 21, 22, 23, 24

## FH52-40S-0.5SH
designator J?
FPC Connector, 0.5mm, 40x1, SMT; Manufacturer: Hirose Electric Co. Ltd.; SymbolCreator: Altium; CompType: FFC or FPC; Pitch_mm: 0.5; Gender: Female; Row_Count: 1; ContactFinish: Gold; Voltage_V: 50; Cert_UL: Y
footprint Hirose_FH52-40S-0_5SH
pins: 1, 2, 3, 4, 5, 6, 7, 8, 9, 10, 11, 12, 13, 14, 15, 16, 17, 18, 19, 20, 21, 22, 23, 24, 25, 26, 27, 28, 29, 30, 31, 32, 33, 34, 35, 36, 37, 38, 39, 40, MP1, MP2

## FH52-60S-0.5SH
designator J?
Connector, FFC/FPC, 60x1, 0.5mm, SMD; Manufacturer: Hirose Electric Co. Ltd.; SymbolCreator: a0799628; CompType: FFC or FPC
footprint HIROSE_FH52-60S-0_5SH
pins: 1, 2, 3, 4, 5, 6, 7, 8, 9, 10, 11, 12, 13, 14, 15, 16, 17, 18, 19, 20, 21, 22, 23, 24, 25, 26, 27, 28, 29, 30, 31, 32, 33, 34, 35, 36, 37, 38, 39, 40, 41, 42, 43, 44, 45, 46, 47, 48, 49, 50, 51, 52, 53, 54, 55, 56, 57, 58, 59, 60

## FX2-100S-1.27DS
designator J?
Connector,  Receptacle, 100-pos, R/A, 1.27mm, TH; Manufacturer: Hirose Electric Co. Ltd.; SymbolCreator: a0799721
footprint CONN_FX2-100S-1.27DS
pins: A1, A2, A3, A4, A5, A6, A7, A8, A9, A10, A11, A12, A13, A14, A15, A16, A17, A18, A19, A20, A21, A22, A23, A24, A25, A26, A27, A28, A29, A30, A31, A32, A33, A34, A35, A36, A37, A38, A39, A40, A41, A42, A43, A44, A45, A46, A47, A48, A49, A50, B1, B2, B3, B4, B5, B6, B7, B8, B9, B10, B11, B12, B13, B14, B15, B16, B17, B18, B19, B20, B21, B22, B23, B24 B25, B25, B26, B27, B28, B29, B30, B31, B32, B33, B34, B35, B36, B37, B38, B39, B40, B41, B42, B43, B44, B45, B46, B47, B48, B49, B50

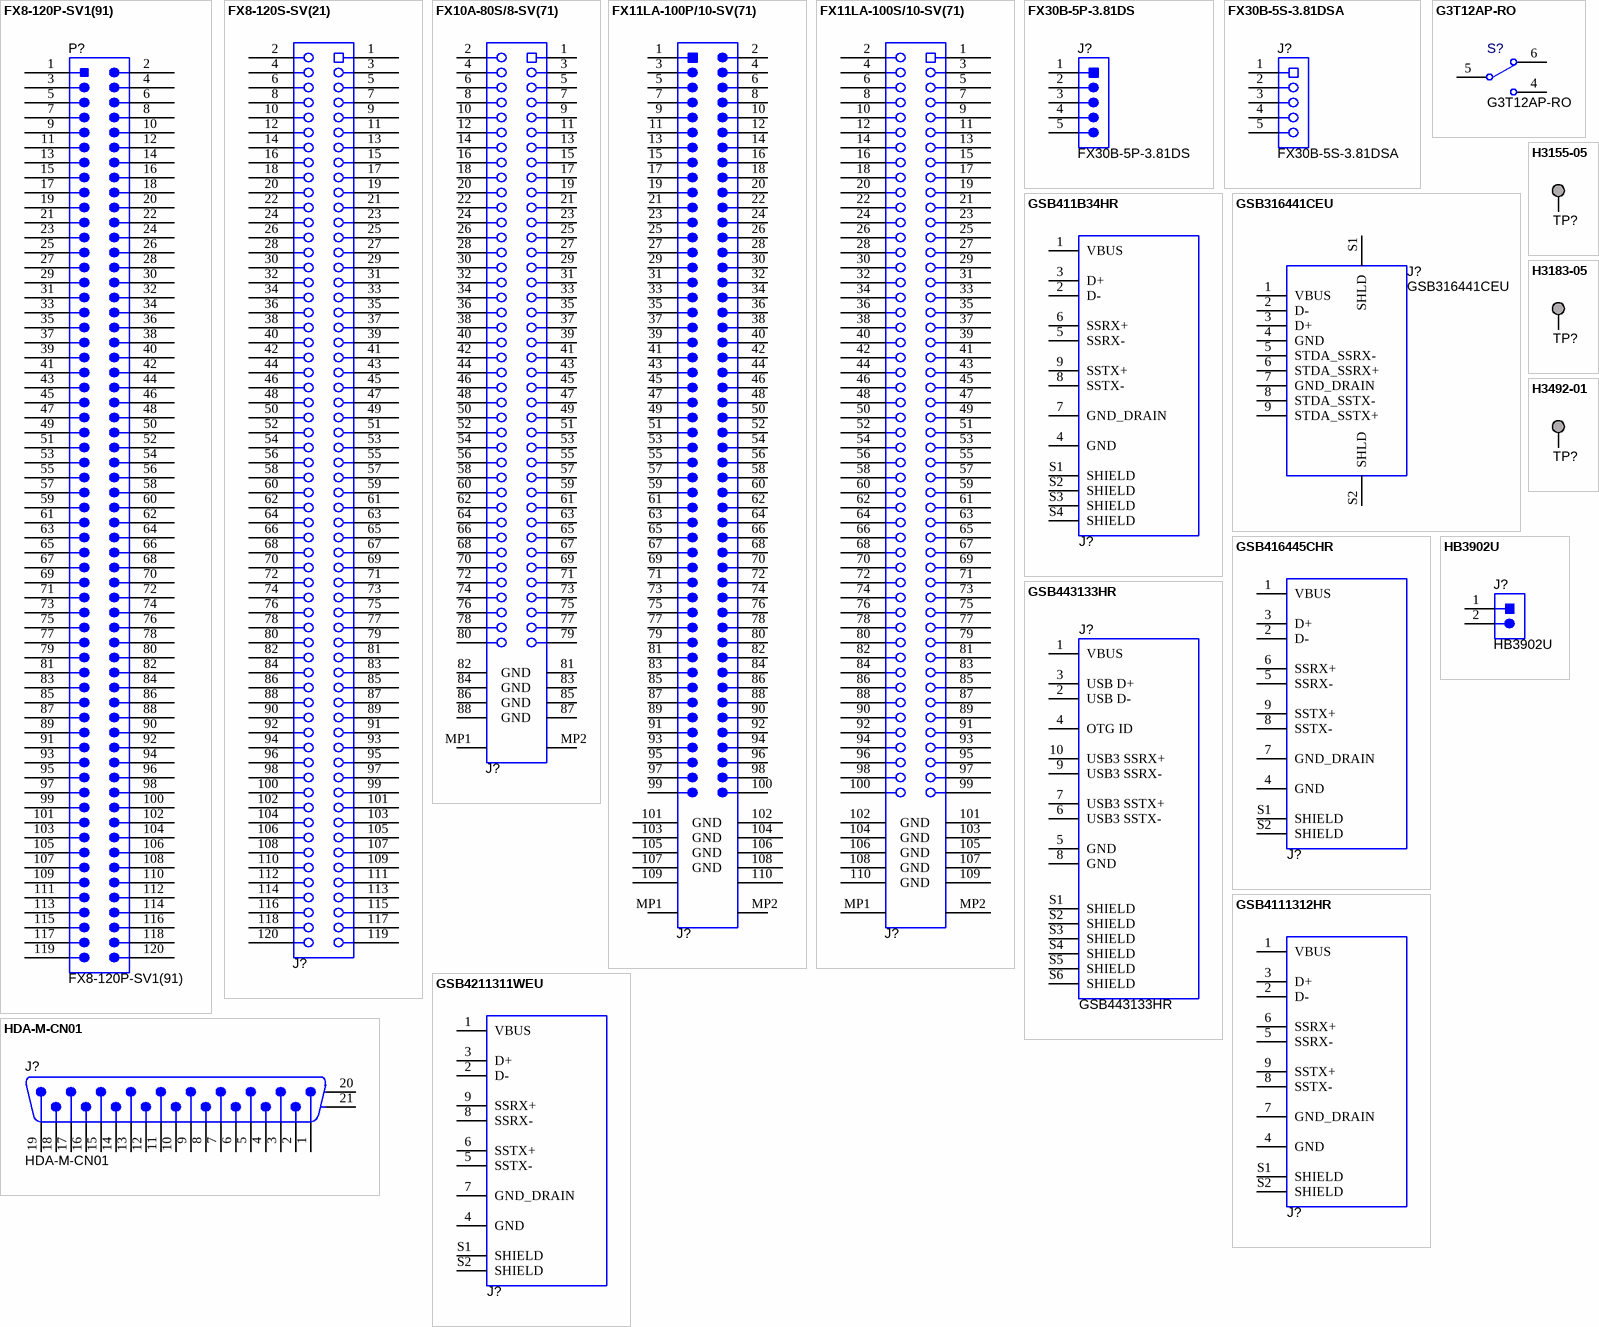
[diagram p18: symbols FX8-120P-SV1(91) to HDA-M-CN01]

## FX8-120P-SV1(91)
designator P?
Header(shrouded), 0.6mm, 60x2, Gold, SMT; Manufacturer: Hirose Electric Co. Ltd.; SymbolCreator: Altium; Pitch_mm: 0.6; Gender: Male; Shrouded: Y; Row_Count: 2; Current_A: 0.4; Voltage_V: 100
footprint Hirose_FX8-120P-SV1
pins: 1, 2, 3, 4, 5, 6, 7, 8, 9, 10, 11, 12, 13, 14, 15, 16, 17, 18, 19, 20, 21, 22, 23, 24, 25, 26, 27, 28, 29, 30, 31, 32, 33, 34, 35, 36, 37, 38, 39, 40, 41, 42, 43, 44, 45, 46, 47, 48, 49, 50, 51, 52, 53, 54, 55, 56, 57, 58, 59, 60, 61, 62, 63, 64, 65, 66, 67, 68, 69, 70, 71, 72, 73, 74, 75, 76, 77, 78, 79, 80, 81, 82, 83, 84, 85, 86, 87, 88, 89, 90, 91, 92, 93, 94, 95, 96, 97, 98, 99, 100, 101, 102, 103, 104, 105, 106, 107, 108, 109, 110, 111, 112, 113, 114, 115, 116, 117, 118, 119, 120

## FX8-120S-SV(21)
designator J?  (value not drawn)
Receptacle, 0.6mm, 60x2, Gold, SMT; Manufacturer: Hirose Electric Co. Ltd.; SymbolCreator: Altium; Pitch_mm: 0.6; Gender: Female; Row_Count: 2; RowSpacing_mm: 5.7; Current_A: 0.4; Voltage_V: 100; Cert_UL: Y
footprint Hirose_FX8-120S-SV
pins: 1, 2, 3, 4, 5, 6, 7, 8, 9, 10, 11, 12, 13, 14, 15, 16, 17, 18, 19, 20, 21, 22, 23, 24, 25, 26, 27, 28, 29, 30, 31, 32, 33, 34, 35, 36, 37, 38, 39, 40, 41, 42, 43, 44, 45, 46, 47, 48, 49, 50, 51, 52, 53, 54, 55, 56, 57, 58, 59, 60, 61, 62, 63, 64, 65, 66, 67, 68, 69, 70, 71, 72, 73, 74, 75, 76, 77, 78, 79, 80, 81, 82, 83, 84, 85, 86, 87, 88, 89, 90, 91, 92, 93, 94, 95, 96, 97, 98, 99, 100, 101, 102, 103, 104, 105, 106, 107, 108, 109, 110, 111, 112, 113, 114, 115, 116, 117, 118, 119, 120

## FX10A-80S/8-SV(71)
designator J?  (value not drawn)
Receptacle, 0.5mm, 40x2, Gold, SMT; Manufacturer: Hirose Electric Co. Ltd.; SymbolCreator: Altium; Pitch_mm: 0.5; Gender: Female; Row_Count: 2; Current_A: 0.3; Voltage_V: 50; Cert_UL: Y
footprint Hirose_FX10x-80S_8-SV
pins: 1, 2, 3, 4, 5, 6, 7, 8, 9, 10, 11, 12, 13, 14, 15, 16, 17, 18, 19, 20, 21, 22, 23, 24, 25, 26, 27, 28, 29, 30, 31, 32, 33, 34, 35, 36, 37, 38, 39, 40, 41, 42, 43, 44, 45, 46, 47, 48, 49, 50, 51, 52, 53, 54, 55, 56, 57, 58, 59, 60, 61, 62, 63, 64, 65, 66, 67, 68, 69, 70, 71, 72, 73, 74, 75, 76, 77, 78, 79, 80, 81 GND, 82 GND, 83 GND, 84 GND, 85 GND, 86 GND, 87 GND, 88 GND, MP1, MP2

## FX11LA-100P/10-SV(71)
designator J?  (value not drawn)
Header, 0.5mm, 50x2, Gold, SMT; Manufacturer: Hirose Electric Co. Ltd.; SymbolCreator: Altium; Pitch_mm: 0.5; Gender: Male; Shrouded: Y; Row_Count: 2; Current_A: 0.3; Voltage_V: 50
footprint Hirose_FX11x-100P_10-SV
pins: 1, 2, 3, 4, 5, 6, 7, 8, 9, 10, 11, 12, 13, 14, 15, 16, 17, 18, 19, 20, 21, 22, 23, 24, 25, 26, 27, 28, 29, 30, 31, 32, 33, 34, 35, 36, 37, 38, 39, 40, 41, 42, 43, 44, 45, 46, 47, 48, 49, 50, 51, 52, 53, 54, 55, 56, 57, 58, 59, 60, 61, 62, 63, 64, 65, 66, 67, 68, 69, 70, 71, 72, 73, 74, 75, 76, 77, 78, 79, 80, 81, 82, 83, 84, 85, 86, 87, 88, 89, 90, 91, 92, 93, 94, 95, 96, 97, 98, 99, 100, 101 GND, 102 GND, 103 GND, 104 GND, 105 GND, 106 GND, 107 GND, 108 GND, 109 GND, 110 GND, MP1, MP2

## FX11LA-100S/10-SV(71)
designator J?  (value not drawn)
Receptacle, 0.5mm, 50x2, Gold, SMT; Manufacturer: Hirose Electric Co. Ltd.; SymbolCreator: Altium; Pitch_mm: 0.5; Gender: Female; Row_Count: 2; Current_A: 0.3; Voltage_V: 50; Cert_UL: Y
footprint Hirose_FX11x-100S_10-SV
pins: 1, 2, 3, 4, 5, 6, 7, 8, 9, 10, 11, 12, 13, 14, 15, 16, 17, 18, 19, 20, 21, 22, 23, 24, 25, 26, 27, 28, 29, 30, 31, 32, 33, 34, 35, 36, 37, 38, 39, 40, 41, 42, 43, 44, 45, 46, 47, 48, 49, 50, 51, 52, 53, 54, 55, 56, 57, 58, 59, 60, 61, 62, 63, 64, 65, 66, 67, 68, 69, 70, 71, 72, 73, 74, 75, 76, 77, 78, 79, 80, 81, 82, 83, 84, 85, 86, 87, 88, 89, 90, 91, 92, 93, 94, 95, 96, 97, 98, 99, 100, 101 GND, 102 GND, 103 GND, 104 GND, 105 GND, 106 GND, 107 GND, 108 GND, 109 GND, 110 GND, MP1, MP2

## FX30B-5P-3.81DS
designator J?
Header(Shrouded), 3.81mm, 5x1, Gold, R/A, TH; Manufacturer: Hirose Electric Co. Ltd.; SymbolCreator: a0412235; Pitch_mm: 3.81; Gender: Male; Shrouded: Y; Row_Count: 1; Current_A: 13; Voltage_V: 250; Cert_CSA: N
footprint Hirose_FX30B-5P-3_81DS
pins: 1, 2, 3, 4, 5

## FX30B-5S-3.81DSA
designator J?
Receptacle, 3.81mm, 5x1, Gold, TH; Manufacturer: Hirose Electric Co. Ltd.; SymbolCreator: a0412235; Pitch_mm: 3.81; Gender: Female; Row_Count: 1; Current_A: 13; Voltage_V: 250; Cert_CSA: N; Cert_UL: Y
footprint Hirose_FX30B-5S-3_81DSA
pins: 1, 2, 3, 4, 5

## G3T12AP-RO
designator S?
Toggle, Actuator, SPDT, SMT; Manufacturer: NKK Switches; SymbolCreator: a0412235
footprint G3T12AP-RO
pins: 4, 5, 6

## GSB411B34HR
designator J?  (value not drawn)
Connector, Receptacle, USB 3.1 Type A, Gold, R/A, Blue, TH; Manufacturer: Amphenol Canada; SymbolCreator: Altium; Gender: Female; Row_Count: 2; RowSpacing_mm: 1.5; Cert_UL: Y
footprint Amphenol_GSB411B34HR
pins: 1 VBUS, 2 D-, 3 D+, 4 GND, 5 SSRX-, 6 SSRX+, 7 GND_DRAIN, 8 SSTX-, 9 SSTX+, S1 SHIELD, S2 SHIELD, S3 SHIELD, S4 SHIELD

## GSB316441CEU
designator J?
Connector, Receptacle, USB Type A, R/A, Blue, SMT; Manufacturer: Amphenol Canada; SymbolCreator: a0799628; Pitch_mm: 1; Gender: Female; ContactFinish: Gold; Cert_UL: Y
footprint Amphenol_GSB316441CEU
pins: 1 VBUS "+5V", 2 D- "Data -", 3 D+ "Data +", 4 GND "Ground", 5 STDA_SSRX-, 6 STDA_SSRX+, 7 GND_DRAIN, 8 STDA_SSTX-, 9 STDA_SSTX+, S1 SHLD, S2 SHLD

## GSB416445CHR
designator J?  (value not drawn)
Connector, Receptacle, USB Type A, R/A, Blue, SMT; Manufacturer: Amphenol Canada; SymbolCreator: Altium; Pitch_mm: 1; Gender: Female; ContactFinish: Tin; Cert_UL: Y
footprint Amphenol_GSB416445CHR
pins: 1 VBUS, 2 D-, 3 D+, 4 GND, 5 SSRX-, 6 SSRX+, 7 GND_DRAIN, 8 SSTX-, 9 SSTX+, S1 SHIELD, S2 SHIELD

## GSB443133HR
designator J?
Connector, Receptacle, USB 3.1 Micro B, R/A, Gold, SMT; Manufacturer: Amphenol Canada; SymbolCreator: Altium; Pitch_mm: 0.65; Gender: Female; Shrouded: Y
footprint Amphenol_GSB443133HR
pins: 1 VBUS, 2 USB D-, 3 USB D+, 4 OTG ID, 5 GND, 6 USB3 SSTX-, 7 USB3 SSTX+, 8 GND, 9 USB3 SSRX-, 10 USB3 SSRX+, S1 SHIELD, S2 SHIELD, S3 SHIELD, S4 SHIELD, S5 SHIELD, S6 SHIELD

## GSB4111312HR
designator J?  (value not drawn)
Connector, Receptacle, USB 3.1 Type A, R/A, TH; Manufacturer: Amphenol Canada; SymbolCreator: Altium; Pitch_mm: 2; Gender: Female; RowSpacing_mm: 1.5; ContactFinish: Gold; Green_Lifecycle: Not Set; Green_REACh: Incomplete
footprint Amphenol_GSB4111312HR
pins: 1 VBUS, 2 D-, 3 D+, 4 GND, 5 SSRX-, 6 SSRX+, 7 GND_DRAIN, 8 SSTX-, 9 SSTX+, S1 SHIELD, S2 SHIELD

## GSB4211311WEU
designator J?  (value not drawn)
Connector, Receptacle, USB 3.1 Type B, R/A, TH; Manufacturer: Amphenol Canada; SymbolCreator: Altium; Gender: Female; Row_Count: 3; RowSpacing_mm: 2; Green_Lifecycle: Not Set; Green_REACh: Incomplete
footprint Amphenol_GSB4211311WEU
pins: 1 VBUS, 2 D-, 3 D+, 4 GND, 5 SSTX-, 6 SSTX+, 7 GND_DRAIN, 8 SSRX-, 9 SSRX+, S1 SHIELD, S2 SHIELD

## H3155-05
designator TP?, comment Suggest using a net name here  (value not drawn)
Pin Receptacle, Dia 1.42mm, Gold, TH; PartNumber: H3155-05; Manufacturer: Harwin; Gender: Female; Current_A: 2
footprint Harwin_H3155-05
pins: 1

## H3183-05
designator TP?, comment Suggest using a net name here  (value not drawn)
Pin Receptacle, 1.00mm Scoket, Gold, TH; PartNumber: H3183-05; Manufacturer: Harwin; Gender: Female
footprint Harwin_H3183-05
pins: 1

## H3492-01
designator TP?, comment Suggest using a net name here  (value not drawn)
Pin Receptacle, Dia 4 mm, Gold, TH; PartNumber: H3492-01; Manufacturer: Harwin; Gender: Female; Current_A: 20
footprint Harwin_H3492-01
pins: 1

## HB3902U
designator J?
Header, 2.54mm, 2x1, Gold, TH; Manufacturer: Foxconn; SymbolCreator: a0412235; Pitch_mm: 2.54; Gender: Male; Shrouded: N; Row_Count: 1; Current_A: 3; Voltage_V: 500; Cert_UL: Y
footprint Foxconn_HB3902U
pins: 1, 2
1 alternate drawing of the same symbol

## HDA-M-CN01
designator J?
HDMI Type A Plug, 1 mm, Black, TH; Manufacturer: Bossconn; SymbolCreator: Altium
footprint BossConn_HDA-M-CN01
pins: 1, 2, 3, 4, 5, 6, 7, 8, 9, 10, 11, 12, 13, 14, 15, 16, 17, 18, 19, 20, 21

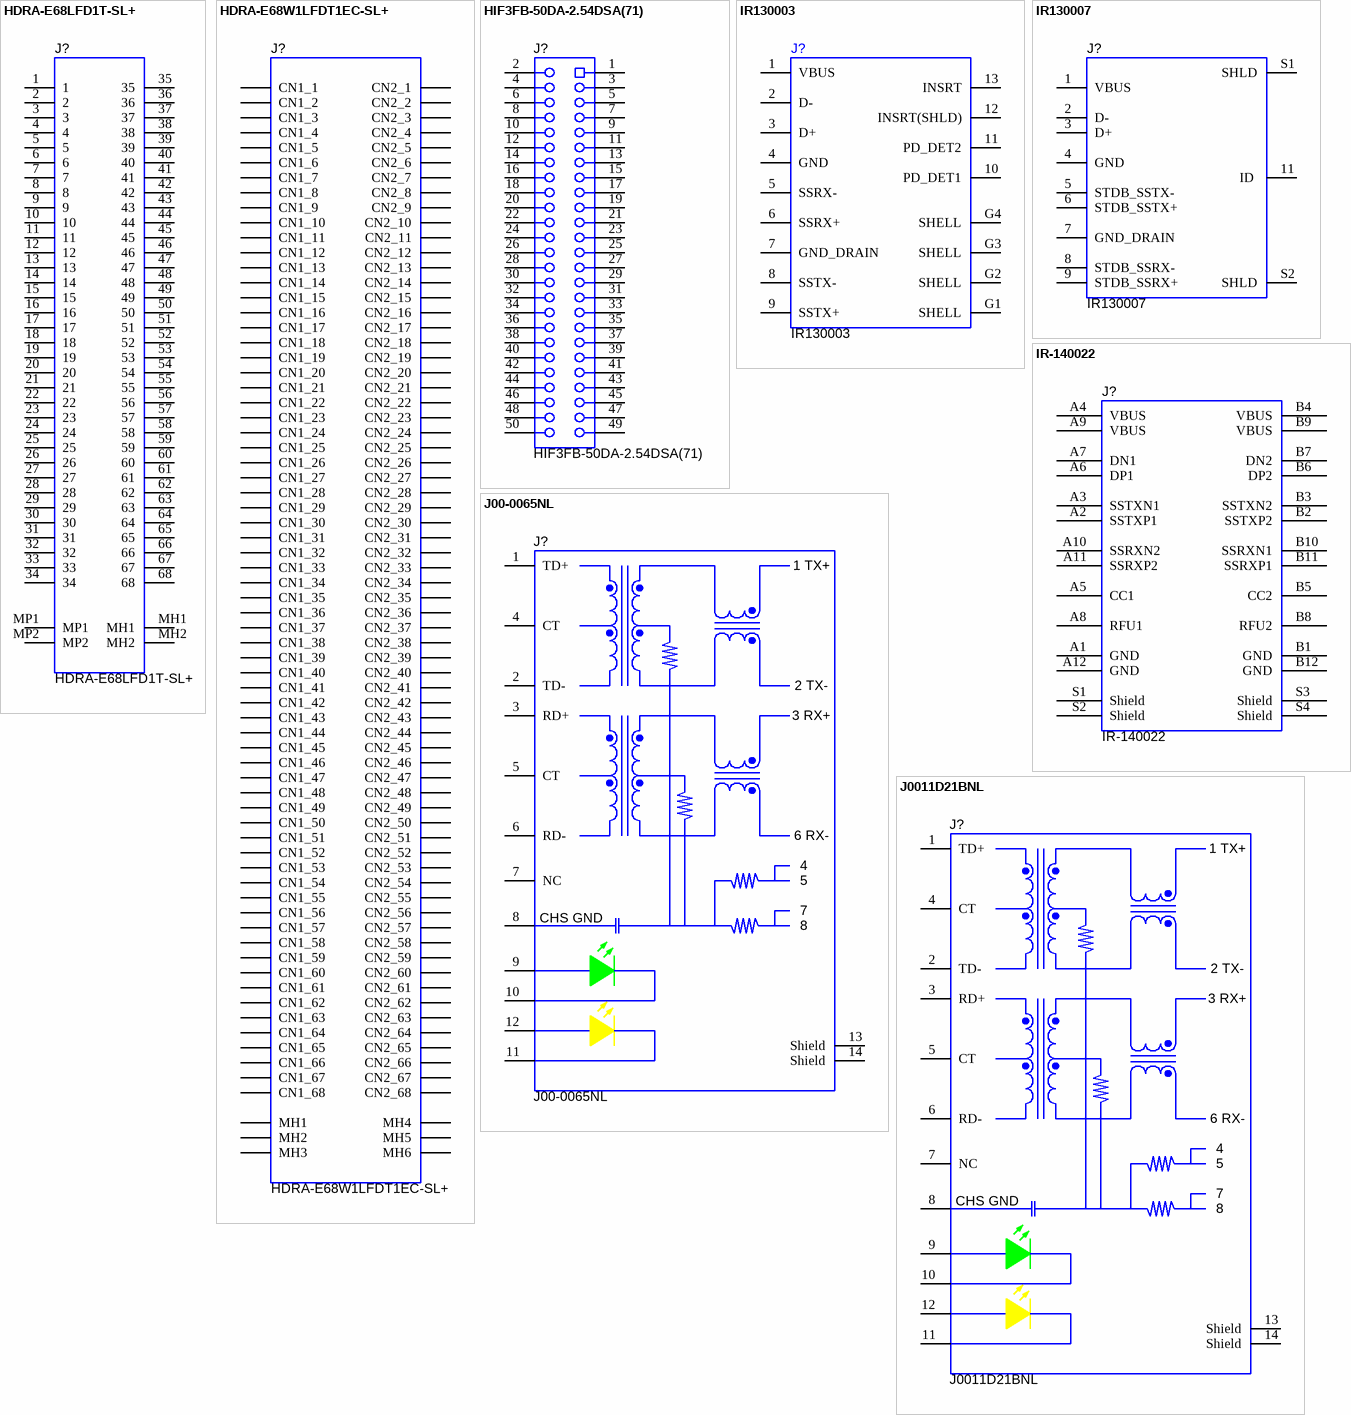
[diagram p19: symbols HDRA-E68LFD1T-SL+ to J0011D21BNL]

## HDRA-E68LFD1T-SL+
designator J?
Female Connector, 0.3 A, 68-Pin, 0.8mm Pitch, R/A, TH, RoHS; Manufacturer: Honda Tsushin Kogyo; SymbolCreator: Altium; CompType: Receptacle
footprint HTK_HDRA-E68LFD1T-SL+
pins: 1, 2, 3, 4, 5, 6, 7, 8, 9, 10, 11, 12, 13, 14, 15, 16, 17, 18, 19, 20, 21, 22, 23, 24, 25, 26, 27, 28, 29, 30, 31, 32, 33, 34, 35, 36, 37, 38, 39, 40, 41, 42, 43, 44, 45, 46, 47, 48, 49, 50, 51, 52, 53, 54, 55, 56, 57, 58, 59, 60, 61, 62, 63, 64, 65, 66, 67, 68, MH1, MH2, MP1, MP2

## HDRA-E68W1LFDT1EC-SL+
designator J?
Female Connector, 0.3 A, 68x2-Pin, 0.8mm Pitch, R/A, TH, RoHS; Manufacturer: Honda Tsushin Kogyo; SymbolCreator: Altium; CompType: Receptacle
footprint HTK_HDRA-E68W1LFDT1EC-SL+
pins: CN1_1, CN1_2, CN1_3, CN1_4, CN1_5, CN1_6, CN1_7, CN1_8, CN1_9, CN1_10, CN1_11, CN1_12, CN1_13, CN1_14, CN1_15, CN1_16, CN1_17, CN1_18, CN1_19, CN1_20, CN1_21, CN1_22, CN1_23, CN1_24, CN1_25, CN1_26, CN1_27, CN1_28, CN1_29, CN1_30, CN1_31, CN1_32, CN1_33, CN1_34, CN1_35, CN1_36, CN1_37, CN1_38, CN1_39, CN1_40, CN1_41, CN1_42, CN1_43, CN1_44, CN1_45, CN1_46, CN1_47, CN1_48, CN1_49, CN1_50, CN1_51, CN1_52, CN1_53, CN1_54, CN1_55, CN1_56, CN1_57, CN1_58, CN1_59, CN1_60, CN1_61, CN1_62, CN1_63, CN1_64, CN1_65, CN1_66, CN1_67, CN1_68, CN2_1, CN2_2, CN2_3, CN2_4, CN2_5, CN2_6, CN2_7, CN2_8, CN2_9, CN2_10, CN2_11, CN2_12, CN2_13, CN2_14, CN2_15, CN2_16, CN2_17, CN2_18, CN2_19, CN2_20, CN2_21, CN2_22, CN2_23, CN2_24, CN2_25, CN2_26, CN2_27, CN2_28, CN2_29, CN2_30, CN2_31, CN2_32, CN2_33, CN2_34, CN2_35, CN2_36, CN2_37, CN2_38, CN2_39, CN2_40, CN2_41, CN2_42, CN2_43, CN2_44, CN2_45, CN2_46, CN2_47, CN2_48, CN2_49, CN2_50, CN2_51, CN2_52, CN2_53, CN2_54, CN2_55, CN2_56, CN2_57, CN2_58, CN2_59, CN2_60, CN2_61, CN2_62, CN2_63, CN2_64, CN2_65, CN2_66, CN2_67, CN2_68, MH1, MH2, MH3, MH4, MH5, MH6

## HIF3FB-50DA-2.54DSA(71)
designator J?
Receptacle, 2.54mm, 25x2, Gold, TH; Manufacturer: Hirose Electric Co. Ltd.; SymbolCreator: a0412235; Pitch_mm: 2.54; Gender: Female; Row_Count: 2; Current_A: 1; Voltage_V: 200; Cert_UL: Y
footprint Hirose_HIF3FB-50DA-2_54DSA_71
pins: 1, 2, 3, 4, 5, 6, 7, 8, 9, 10, 11, 12, 13, 14, 15, 16, 17, 18, 19, 20, 21, 22, 23, 24, 25, 26, 27, 28, 29, 30, 31, 32, 33, 34, 35, 36, 37, 38, 39, 40, 41, 42, 43, 44, 45, 46, 47, 48, 49, 50

## IR130003
designator J?
Connector, Receptacle, USB 3.0 Type A, R/A, Top Mount TH; Manufacturer: Joinsoon Electronics Manufacturing; SymbolCreator: x0208326; Gender: Female
footprint JEM_IR130003
pins: 1 VBUS, 2 D-, 3 D+, 4 GND, 5 SSRX-, 6 SSRX+, 7 GND_DRAIN, 8 SSTX-, 9 SSTX+, 10 PD_DET1, 11 PD_DET2, 12 INSRT(SHLD), 13 INSRT, G1 SHELL, G2 SHELL, G3 SHELL, G4 SHELL

## IR130007
designator J?
Connector, Receptacle, USB 3.0 Type B, R/A, Top Mount TH; Manufacturer: Joinsoon Electronics Manufacturing; SymbolCreator: a0799628; Gender: Female
footprint JEM_IR130007
pins: 1 VBUS "+5V", 2 D- "Data -", 3 D+ "Data +", 4 GND "Ground", 5 STDB_SSTX-, 6 STDB_SSTX+, 7 GND_DRAIN, 8 STDB_SSRX-, 9 STDB_SSRX+, 11 ID , S1 SHLD, S2 SHLD

## IR-140022
designator J?
Connector, Receptacle, USB Type C, R/A, SMT; Manufacturer: Joinsoon Electronics Manufacturing; SymbolCreator: Altium; Pitch_mm: 0.5; Gender: Female; Shrouded: N; Row_Count: 2; RowSpacing_mm: 1.555
footprint JEM_IR-140022
pins: A1 GND, A2 SSTXP1, A3 SSTXN1, A4 VBUS, A5 CC1, A6 DP1, A7 DN1, A8 RFU1, A9 VBUS, A10 SSRXN2, A11 SSRXP2, A12 GND, B1 GND, B2 SSTXP2, B3 SSTXN2, B4 VBUS, B5 CC2, B6 DP2, B7 DN2, B8 RFU2, B9 VBUS, B10 SSRXN1, B11 SSRXP1, B12 GND, S1 Shield, S2 Shield, S3 Shield, S4 Shield

## J00-0065NL
designator J?
Connector, RJ45 with integrated magnetics, R/A, TH; Manufacturer: Pulse Engineering; SymbolCreator: Altium; Pitch_mm: 2.54; Gender: Female; ContactFinish: Gold; Cert_UL: Y
footprint Pulse_J00-0065NL
pins: 1 TD+, 2 TD-, 3 RD+, 4 CT, 5 CT, 6 RD-, 7 NC, 8 CHS GND (power), 9 LEFT LED ANODE, 10 LEFT LED, 11 RIGHT LED ANODE, 12 RIGHT LED, 13 Shield, 14 Shield
1 alternate drawing of the same symbol

## J0011D21BNL
designator J?
Connector, RJ45 with integrated magnetics, 1x1, Gold, R/A, TH; Manufacturer: Pulse Engineering; SymbolCreator: Altium; Green_Lifecycle: Not Set; Green_REACh: Incomplete
footprint Pulse_J0011D21BNL
pins: 1 TD+, 2 TD-, 3 RD+, 4 CT, 5 CT, 6 RD-, 7 NC, 8 CHS GND (power), 9 LEFT LED ANODE, 10 LEFT LED, 11 RIGHT LED ANODE, 12 RIGHT LED, 13 Shield, 14 Shield
1 alternate drawing of the same symbol

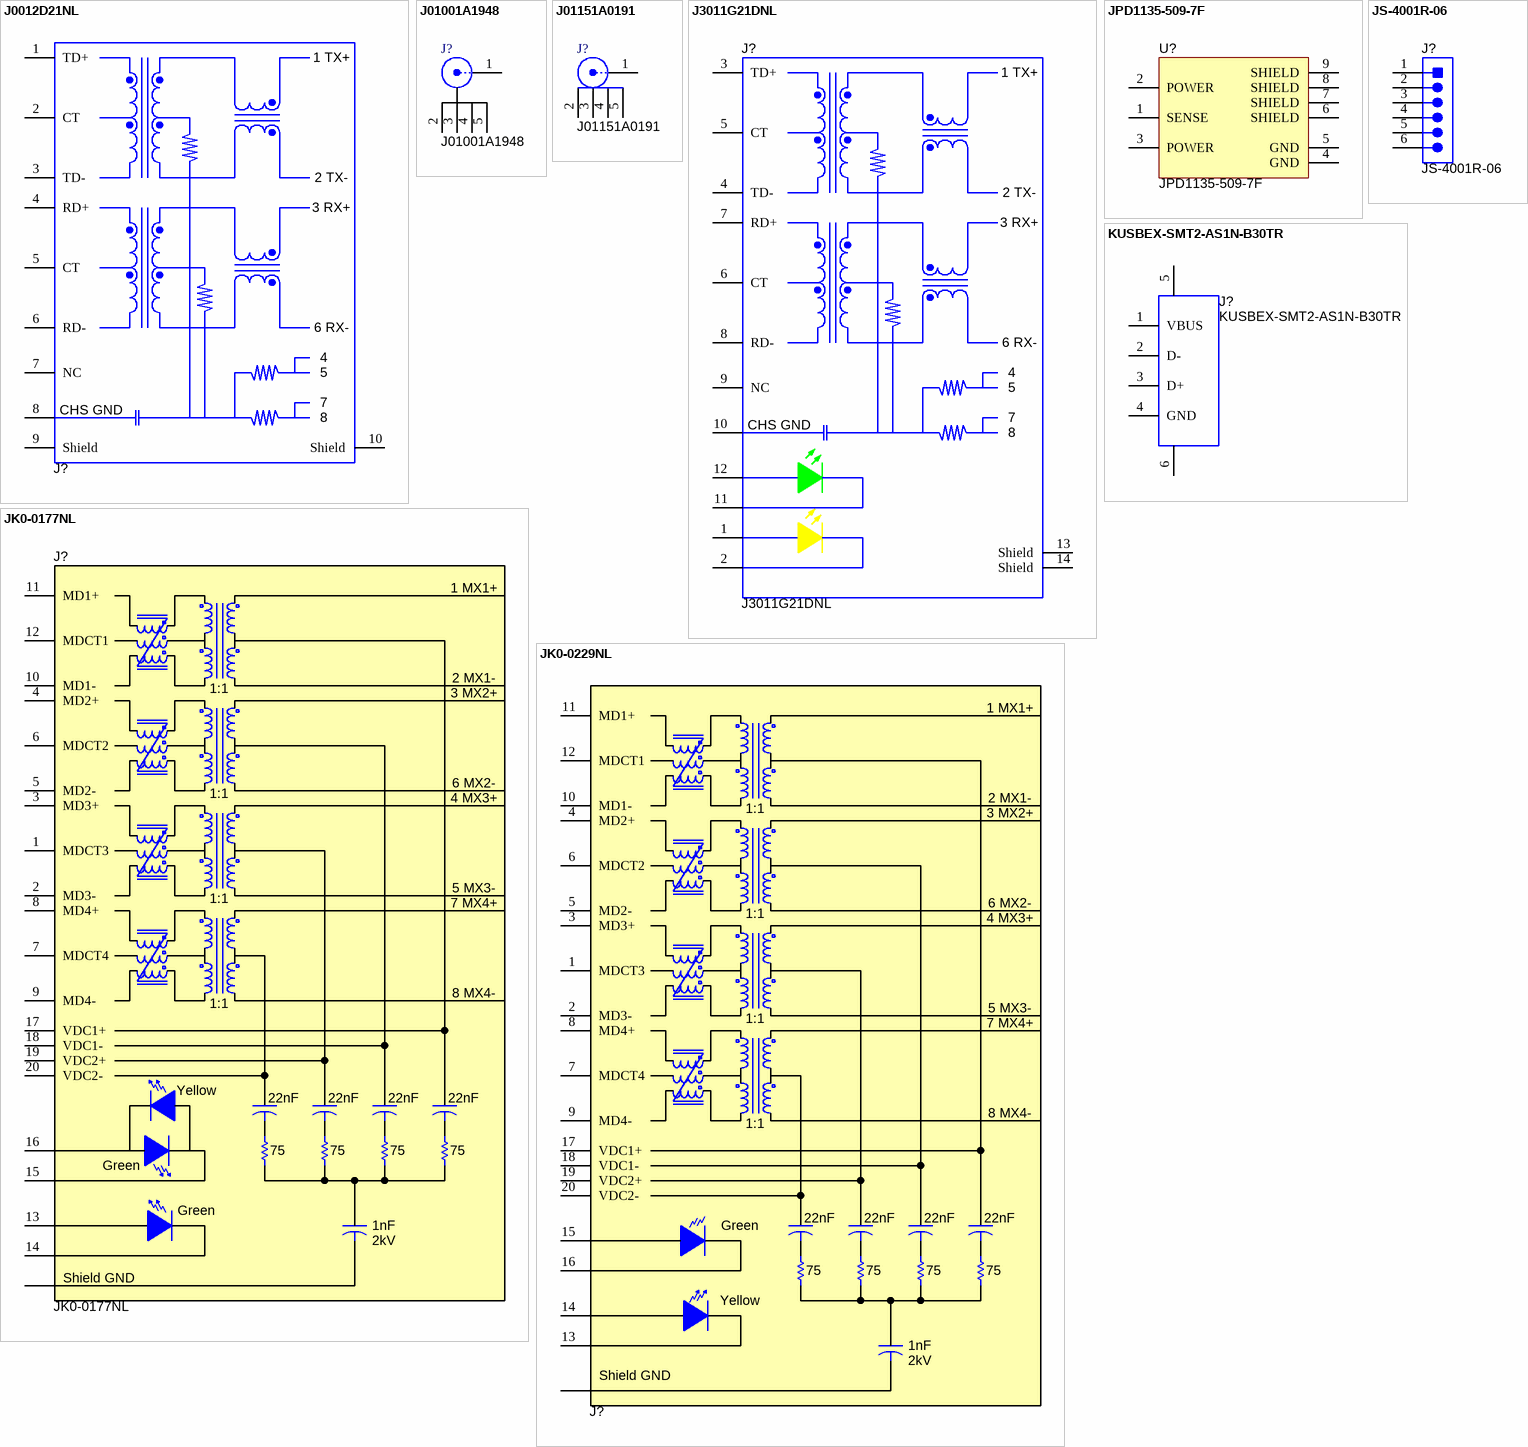
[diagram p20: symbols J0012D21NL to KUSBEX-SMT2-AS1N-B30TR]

## J0012D21NL
designator J?  (value not drawn)
CONN MAGJACK, 1PORT, 100 BASE-TX, TH; Manufacturer: Pulse Engineering; SymbolCreator: Altium; CompType: Connector; Pitch_mm: 1.27; Gender: Female; ContactFinish: Gold
footprint Pulse_J0012D21NL
pins: 1 TD+, 2 CT, 3 TD-, 4 RD+, 5 CT, 6 RD-, 7 NC, 8 CHS GND (power), 9 Shield, 10 Shield

## J01001A1948
designator J?
Connector, BNC Angle Receptacle, TH; Manufacturer: Telegärtner; SymbolCreator: a0799628
footprint Telegaertner_J01001A1948
pins: 1, 2, 3, 4, 5

## J01151A0191
designator J?
SMA Jack, 50Ohm, R/A, TH; Manufacturer: Telegärtner; SymbolCreator: X0208326; Gender: Female; ContactFinish: Gold
footprint Telegaertner_J01151A0191
pins: 1, 2, 3, 4, 5

## J3011G21DNL
designator J?
Connector, RJ45 with integrated magnetics, 1x1, Gold, R/A, SMT; Manufacturer: Pulse Engineering; SymbolCreator: Altium; Pitch_mm: 1.02; Gender: Female; Row_Count: 1
footprint Pulse_J3011G21DNL
pins: 1 RIGHT LED ANODE, 2 RIGHT LED CATHODE, 3 TD+, 4 TD-, 5 CT, 6 CT, 7 RD+, 8 RD-, 9 NC, 10 CHS GND (power), 11 LEFT LED CATHODE, 12 LEFT LED ANODE, 13 Shield, 14 Shield

## JK0-0177NL
designator J?
RJ45 with integrated magnetics; Manufacturer: Pulse Engineering; SymbolCreator: x0208325; Green_Lifecycle: Not Set; Green_REACh: Incomplete
footprint JK0-0177NL
pins: 1 MDCT3, 2 MD3-, 3 MD3+, 4 MD2+, 5 MD2-, 6 MDCT2, 7 MDCT4, 8 MD4+, 9 MD4-, 10 MD1-, 11 MD1+, 12 MDCT1, 13, 14, 15, 16, 17 VDC1+, 18 VDC1-, 19 VDC2+, 20 VDC2-, 21 Shield (power), 22 Shield (power)

## JK0-0229NL
designator J?  (value not drawn)
Connector, RJ45 with integrated magnetics, R/A, TH; Manufacturer: Pulse Engineering; SymbolCreator: Altium; Gender: Female; ContactFinish: Gold; Current_A: 1.37; Voltage_V: 57; Cert_UL: Y
footprint JK0-0177NL
pins: 1 MDCT3, 2 MD3-, 3 MD3+, 4 MD2+, 5 MD2-, 6 MDCT2, 7 MDCT4, 8 MD4+, 9 MD4-, 10 MD1-, 11 MD1+, 12 MDCT1, 13, 14, 15, 16, 17 VDC1+, 18 VDC1-, 19 VDC2+, 20 VDC2-, 21 Shield (power), 22 Shield (power)

## JPD1135-509-7F
designator U?
Connector,  DC Power Jack, R/A, 3 Pos, TH; Manufacturer: Foxconn; SymbolCreator: a0412235; Green_Lifecycle: Not Set; Green_REACh: Incomplete
footprint CONN_JPD1135-509
pins: 1 SENSE, 2 POWER (power), 3 POWER (power), 4 GND (power), 5 GND (power), 6 SHIELD, 7 SHIELD, 8 SHIELD, 9 SHIELD

## JS-4001R-06
designator J?
Header, 3.96mm, 6x1, Tin, R/A, TH; Manufacturer: Chyao-Shiunn; SymbolCreator: a0412235; Pitch_mm: 3.96; Gender: Male; Shrouded: N; Row_Count: 1; Current_A: 7; Voltage_V: 250; Cert_UL: Y
footprint Chyao-Shiunn_JS-4001R-06
pins: 1, 2, 3, 4, 5, 6

## KUSBEX-SMT2-AS1N-B30TR
designator J?
Connector, Receptacle, USB Type A, R/A, SMT; Manufacturer: Kycon Inc; SymbolCreator: a0412235; Pitch_mm: 2; Gender: Female; Row_Count: 1; ContactFinish: Gold
footprint KYCON_KUSBEX-SMT2-AS1N-B30TR
pins: 1 VBUS "+5V", 2 D- "Data -", 3 D+ "Data +", 4 GND "Ground", 5 Shield, 6 Shield

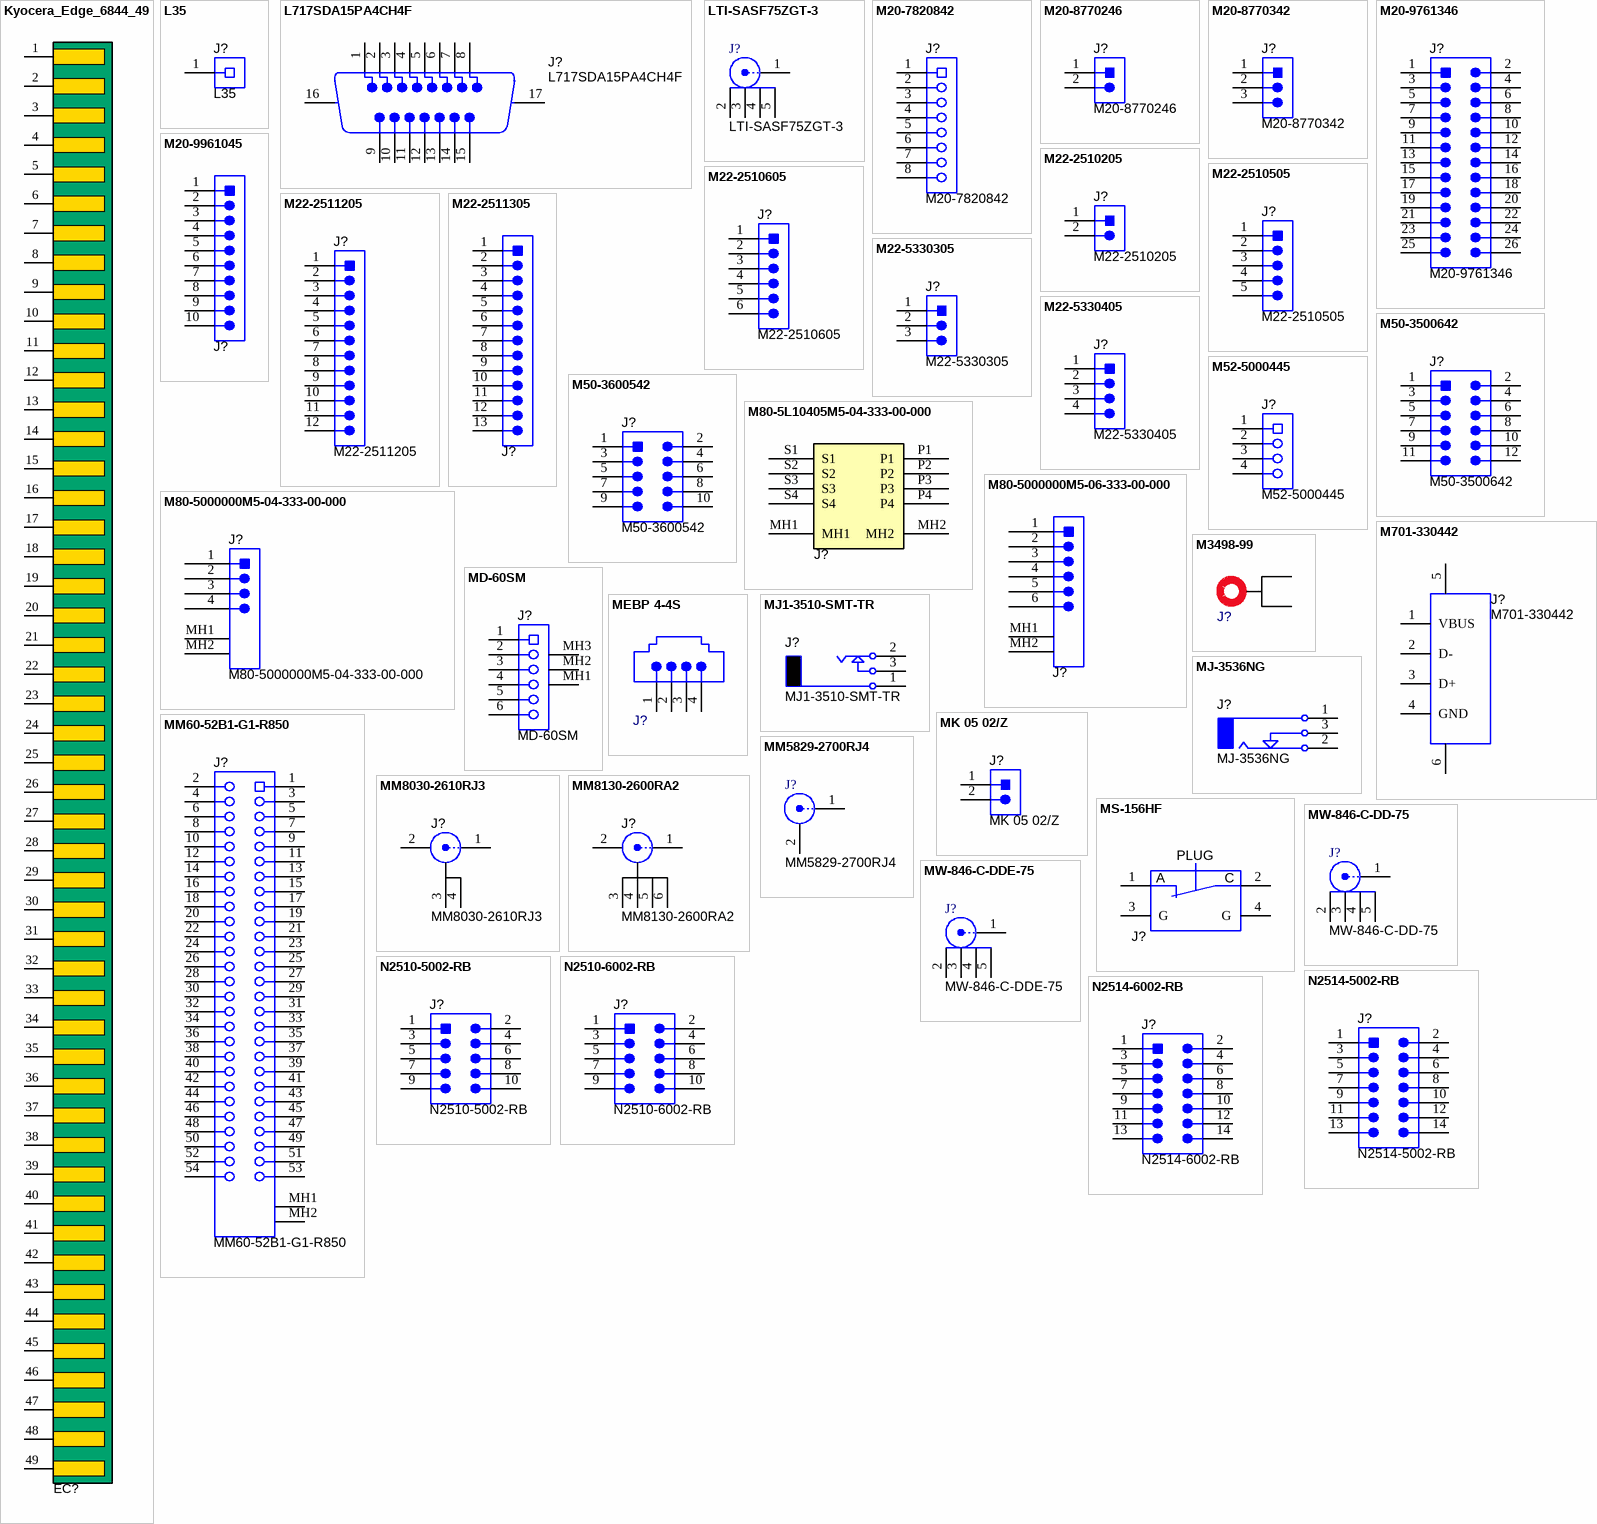
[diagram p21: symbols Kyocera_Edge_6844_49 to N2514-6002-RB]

## Kyocera_Edge_6844_49
designator EC?  (value not drawn)  (no BOM)
Card Edge Footprint, 49-Pos, 0.3mm Pitch; SymbolCreator: Altium; Pitch_mm: 0.3; Gender: Male; Row_Count: 1; Current_A: 0.2; Voltage_V: 50
footprint Kyocera_Edge_6844_49
pins: 1, 2, 3, 4, 5, 6, 7, 8, 9, 10, 11, 12, 13, 14, 15, 16, 17, 18, 19, 20, 21, 22, 23, 24, 25, 26, 27, 28, 29, 30, 31, 32, 33, 34, 35, 36, 37, 38, 39, 40, 41, 42, 43, 44, 45, 46, 47, 48, 49

## L35
designator J?
Connector, L Type Copper Single Conductor, TH; Manufacturer: Thomas & Betts; SymbolCreator: a0799628; Gender: Female; Row_Count: 1; Green_Lifecycle: Active; Green_REACh: Passed
footprint TB_L35
pins: 1

## L717SDA15PA4CH4F
designator J?
D-SUB Header, 2.74mm, 15 Pos, Gold, R/A, TH; Manufacturer: Amphenol Canada; SymbolCreator: x0208325; Pitch_mm: 2.74; Gender: Male; Row_Count: 2; RowSpacing_mm: 2.84; Current_A: 5; Voltage_V: 250; Cert_UL: Y
footprint Amphenol_L717SDA15
pins: 1, 2, 3, 4, 5, 6, 7, 8, 9, 10, 11, 12, 13, 14, 15, 16 MH1, 17 MH2

## LTI-SASF75ZGT-3
designator J?
Connector, SMA End Launch PCB Jack w/tab Termination, 0.030 THK PCB, SMD; Manufacturer: Lighthorse Technologies; SymbolCreator: X0208326
footprint CONN_LTI_SASF55ZGT-3
footprint CONN_LTI_SASF55ZGT-3-RF
pins: 1, 2, 3, 4, 5

## M20-7820842
designator J?
Receptacle, 2.54 mm, 8x1, Gold, TH; Manufacturer: Harwin; SymbolCreator: a0411947; Pitch_mm: 2.54; Gender: Female; Shrouded: N; Row_Count: 1
footprint Harwin_M20-78208
pins: 1, 2, 3, 4, 5, 6, 7, 8

## M20-8770246
designator J?
Header, 2.54mm, 2x1, Tin,  SMT; Manufacturer: Harwin; SymbolCreator: a0412235; Pitch_mm: 2.54; Gender: Male; Shrouded: N; Row_Count: 1; Current_A: 3; Voltage_V: 250; Cert_UL: Y
footprint Harwin_M20-87702
pins: 1, 2
1 alternate drawing of the same symbol

## M20-8770342
designator J?
Header, 2.54mm, 3x1, Gold, SMT; Manufacturer: Harwin; SymbolCreator: a0799628; Pitch_mm: 2.54; Gender: Male; Shrouded: N; Row_Count: 1; Current_A: 3; Cert_UL: Y; Green_Lifecycle: Active; Green_REACh: Passed
footprint Harwin_M20-87703
pins: 1, 2, 3
3 alternate drawings of the same symbol

## M20-9761346
designator J?
Header, 2.54 mm, 13x2, TH; Manufacturer: Harwin; SymbolCreator: a0412235; Pitch_mm: 2.54; Gender: Male; Shrouded: N; Row_Count: 2; ContactFinish: Tin
footprint Harwin_M20-9761346
pins: 1, 2, 3, 4, 5, 6, 7, 8, 9, 10, 11, 12, 13, 14, 15, 16, 17, 18, 19, 20, 21, 22, 23, 24, 25, 26

## M20-9961045
designator J?  (value not drawn)
Header, 2.54 mm, 10x1, TH; Manufacturer: Harwin; SymbolCreator: a0412235; Pitch_mm: 2.54; Gender: Male; Shrouded: N; Row_Count: 1; ContactFinish: Gold; Current_A: 3; Voltage_V: 750; Cert_UL: Y
footprint Harwin_M20-9961045
pins: 1, 2, 3, 4, 5, 6, 7, 8, 9, 10

## M22-2510205
designator J?
Header, 2mm, 2x1, Gold, Black, TH; Manufacturer: Harwin; SymbolCreator: a0412235; Pitch_mm: 2; Gender: Male; Shrouded: N; Row_Count: 1; Voltage_V: 500; Cert_UL: Y
footprint Harwin_M22-2510205
pins: 1, 2
1 alternate drawing of the same symbol

## M22-2510505
designator J?
Header, 2mm, 5x1, Gold, TH; Manufacturer: Harwin; SymbolCreator: a0412235; Pitch_mm: 2; Gender: Male; Shrouded: N; Row_Count: 1; Voltage_V: 500; Cert_UL: Y
footprint Harwin_M22-2510505
pins: 1, 2, 3, 4, 5

## M22-2510605
designator J?
Header, 2mm, 6x1, Gold, TH; Manufacturer: Harwin; SymbolCreator: a0412235; Pitch_mm: 2; Gender: Male; Shrouded: N; Row_Count: 1; Voltage_V: 500
footprint Harwin_M22-25106
pins: 1, 2, 3, 4, 5, 6

## M22-2511205
designator J?
Header, 2mm, 12x1, Gold, TH; Manufacturer: Harwin; SymbolCreator: a0412235; Pitch_mm: 2; Gender: Male; Shrouded: N; Row_Count: 1; Voltage_V: 500; Cert_UL: Y
footprint Harwin_M22-2511205
pins: 1, 2, 3, 4, 5, 6, 7, 8, 9, 10, 11, 12

## M22-2511305
designator J?  (value not drawn)
Header, 2mm, 13x1, Gold, TH; Manufacturer: Harwin; SymbolCreator: a0411947; Pitch_mm: 2; Gender: Male; Shrouded: N; Row_Count: 1; Voltage_V: 500; Cert_UL: Y
footprint Harwin_M22-2511305
pins: 1, 2, 3, 4, 5, 6, 7, 8, 9, 10, 11, 12, 13

## M22-5330305
designator J?
Header, 2mm, 3x1, Gold, Black, R/A, SMT; Manufacturer: Harwin; SymbolCreator: a0799628; Pitch_mm: 2; Gender: Male; Row_Count: 1
footprint Harwin_M22-5330305
pins: 1, 2, 3
3 alternate drawings of the same symbol

## M22-5330405
designator J?
Header, 2mm, 4x1, Gold, Black, R/A, SMT; Manufacturer: Harwin; SymbolCreator: a0412235; Pitch_mm: 2; Gender: Male; Row_Count: 1
footprint Harwin_M22-5330405
pins: 1, 2, 3, 4

## M50-3500642
designator J?
Header, 1.27mm, 6x2, Gold, TH; Manufacturer: Harwin; SymbolCreator: a0412235; Pitch_mm: 1.27; Gender: Male; Shrouded: N; Row_Count: 2; Current_A: 1; Cert_UL: Y
footprint Harwin_M50-3500642
pins: 1, 2, 3, 4, 5, 6, 7, 8, 9, 10, 11, 12
1 alternate drawing of the same symbol

## M50-3600542
designator J?
Header, 1.27mm, 5x2, Gold, SMT; Manufacturer: Harwin; SymbolCreator: a0412235; Pitch_mm: 1.27; Gender: Male; Shrouded: N; Row_Count: 2; Current_A: 1; Voltage_V: 1000; Cert_UL: Y
footprint Harwin_M50-3600542
pins: 1, 2, 3, 4, 5, 6, 7, 8, 9, 10

## M52-5000445
designator J?
Recptacle, 4x1, 1.27mm, TH; Manufacturer: Harwin; SymbolCreator: a0411947; CompType: Receptacle
footprint Harwin_M52-5000445
pins: 1, 2, 3, 4

## M80-5L10405M5-04-333-00-000
designator J?  (value not drawn)
Connector, 4+4, Gold, Black, R/A, TH; Manufacturer: Harwin; SymbolCreator: Altium; Gender: Male; Shrouded: Y; Current_A: 3; Voltage_V: 800
footprint Harwin_M80-5L10405M5-04-333-00-000
pins: MH1, MH2, P1, P2, P3, P4, S1, S2, S3, S4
